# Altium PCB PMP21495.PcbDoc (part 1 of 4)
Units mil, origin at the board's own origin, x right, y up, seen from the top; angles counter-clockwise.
Board outline 10700 x 5800 mil, 6 copper layers (Top Layer, Signal Layer 3, Signal Layer 1, Signal Layer 2, Signal Layer 4, Bottom Layer), stack 66 mil thick; 305 components, 138 nets, 864 pads, 367 vias.
Unrouted connection lines stored in the file: 2.
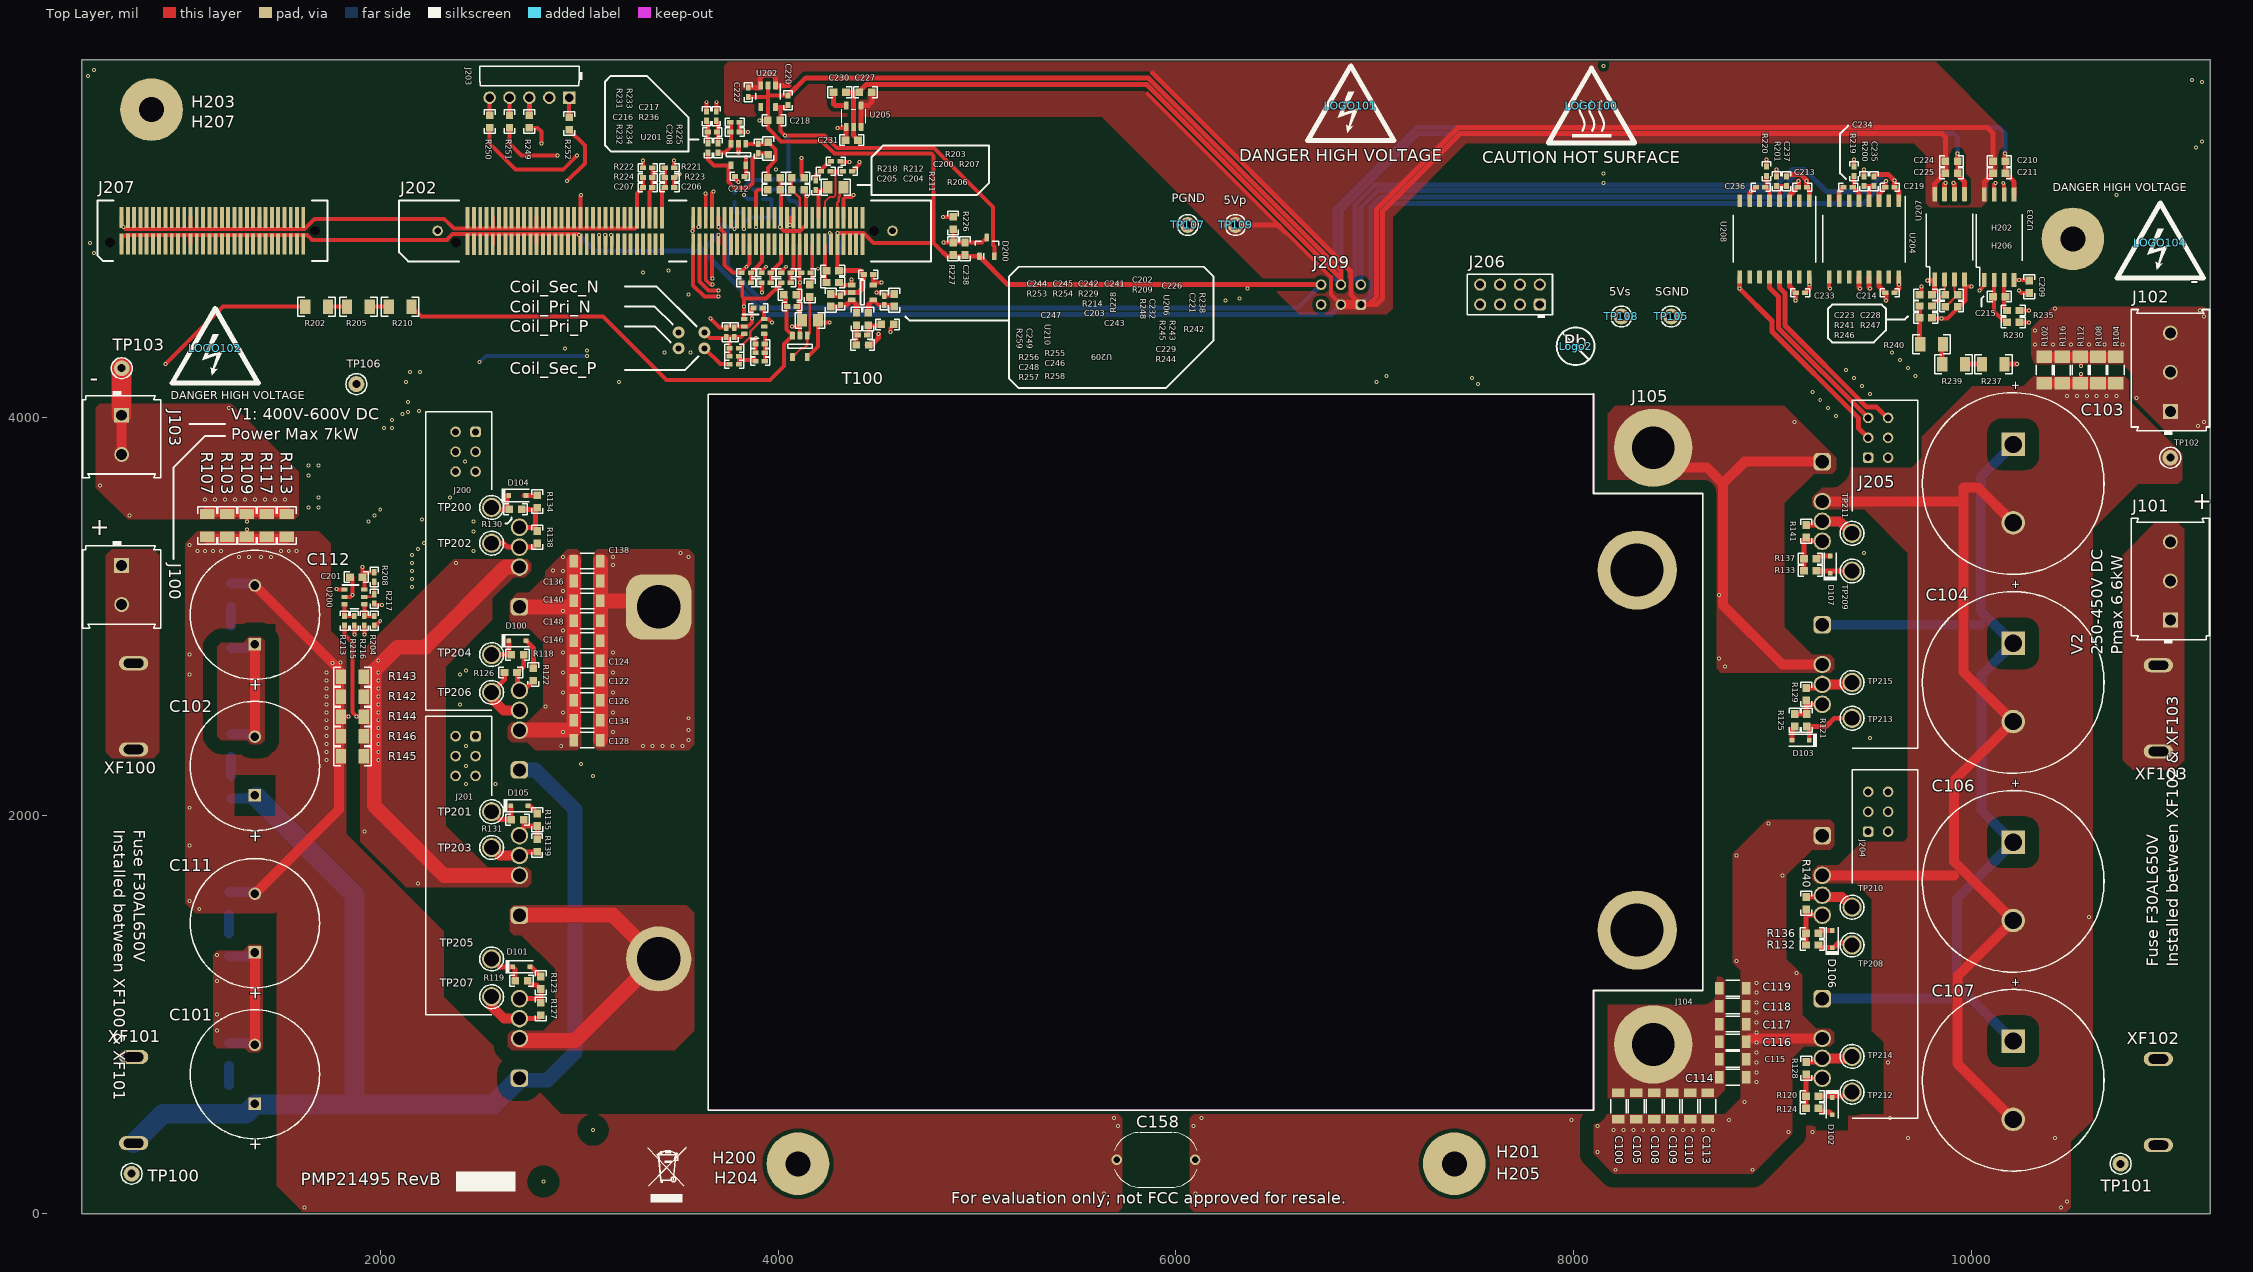
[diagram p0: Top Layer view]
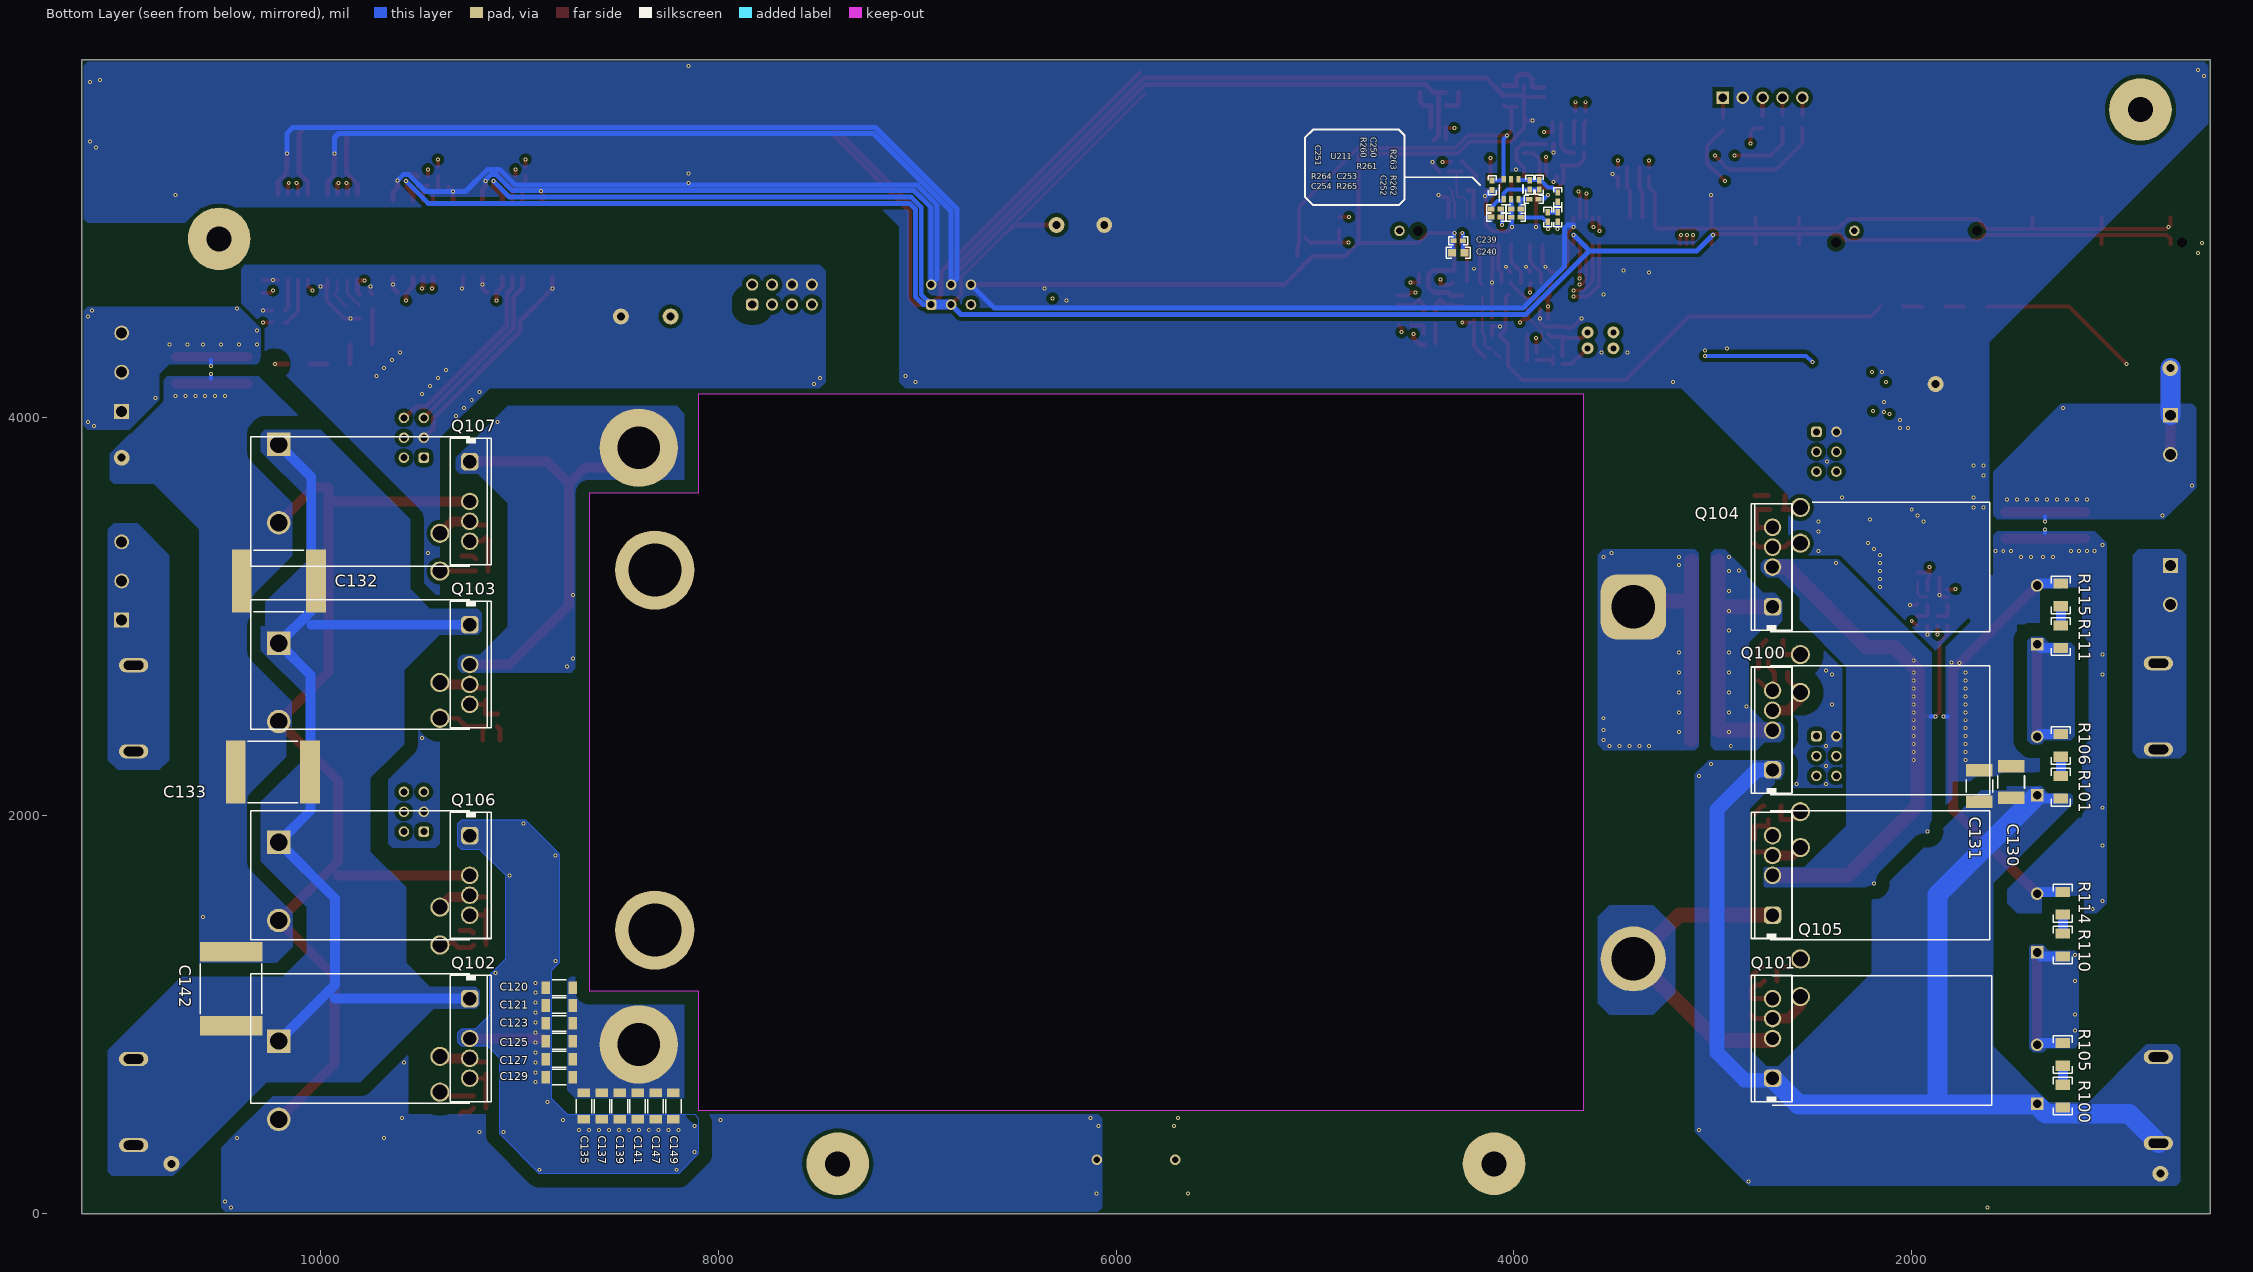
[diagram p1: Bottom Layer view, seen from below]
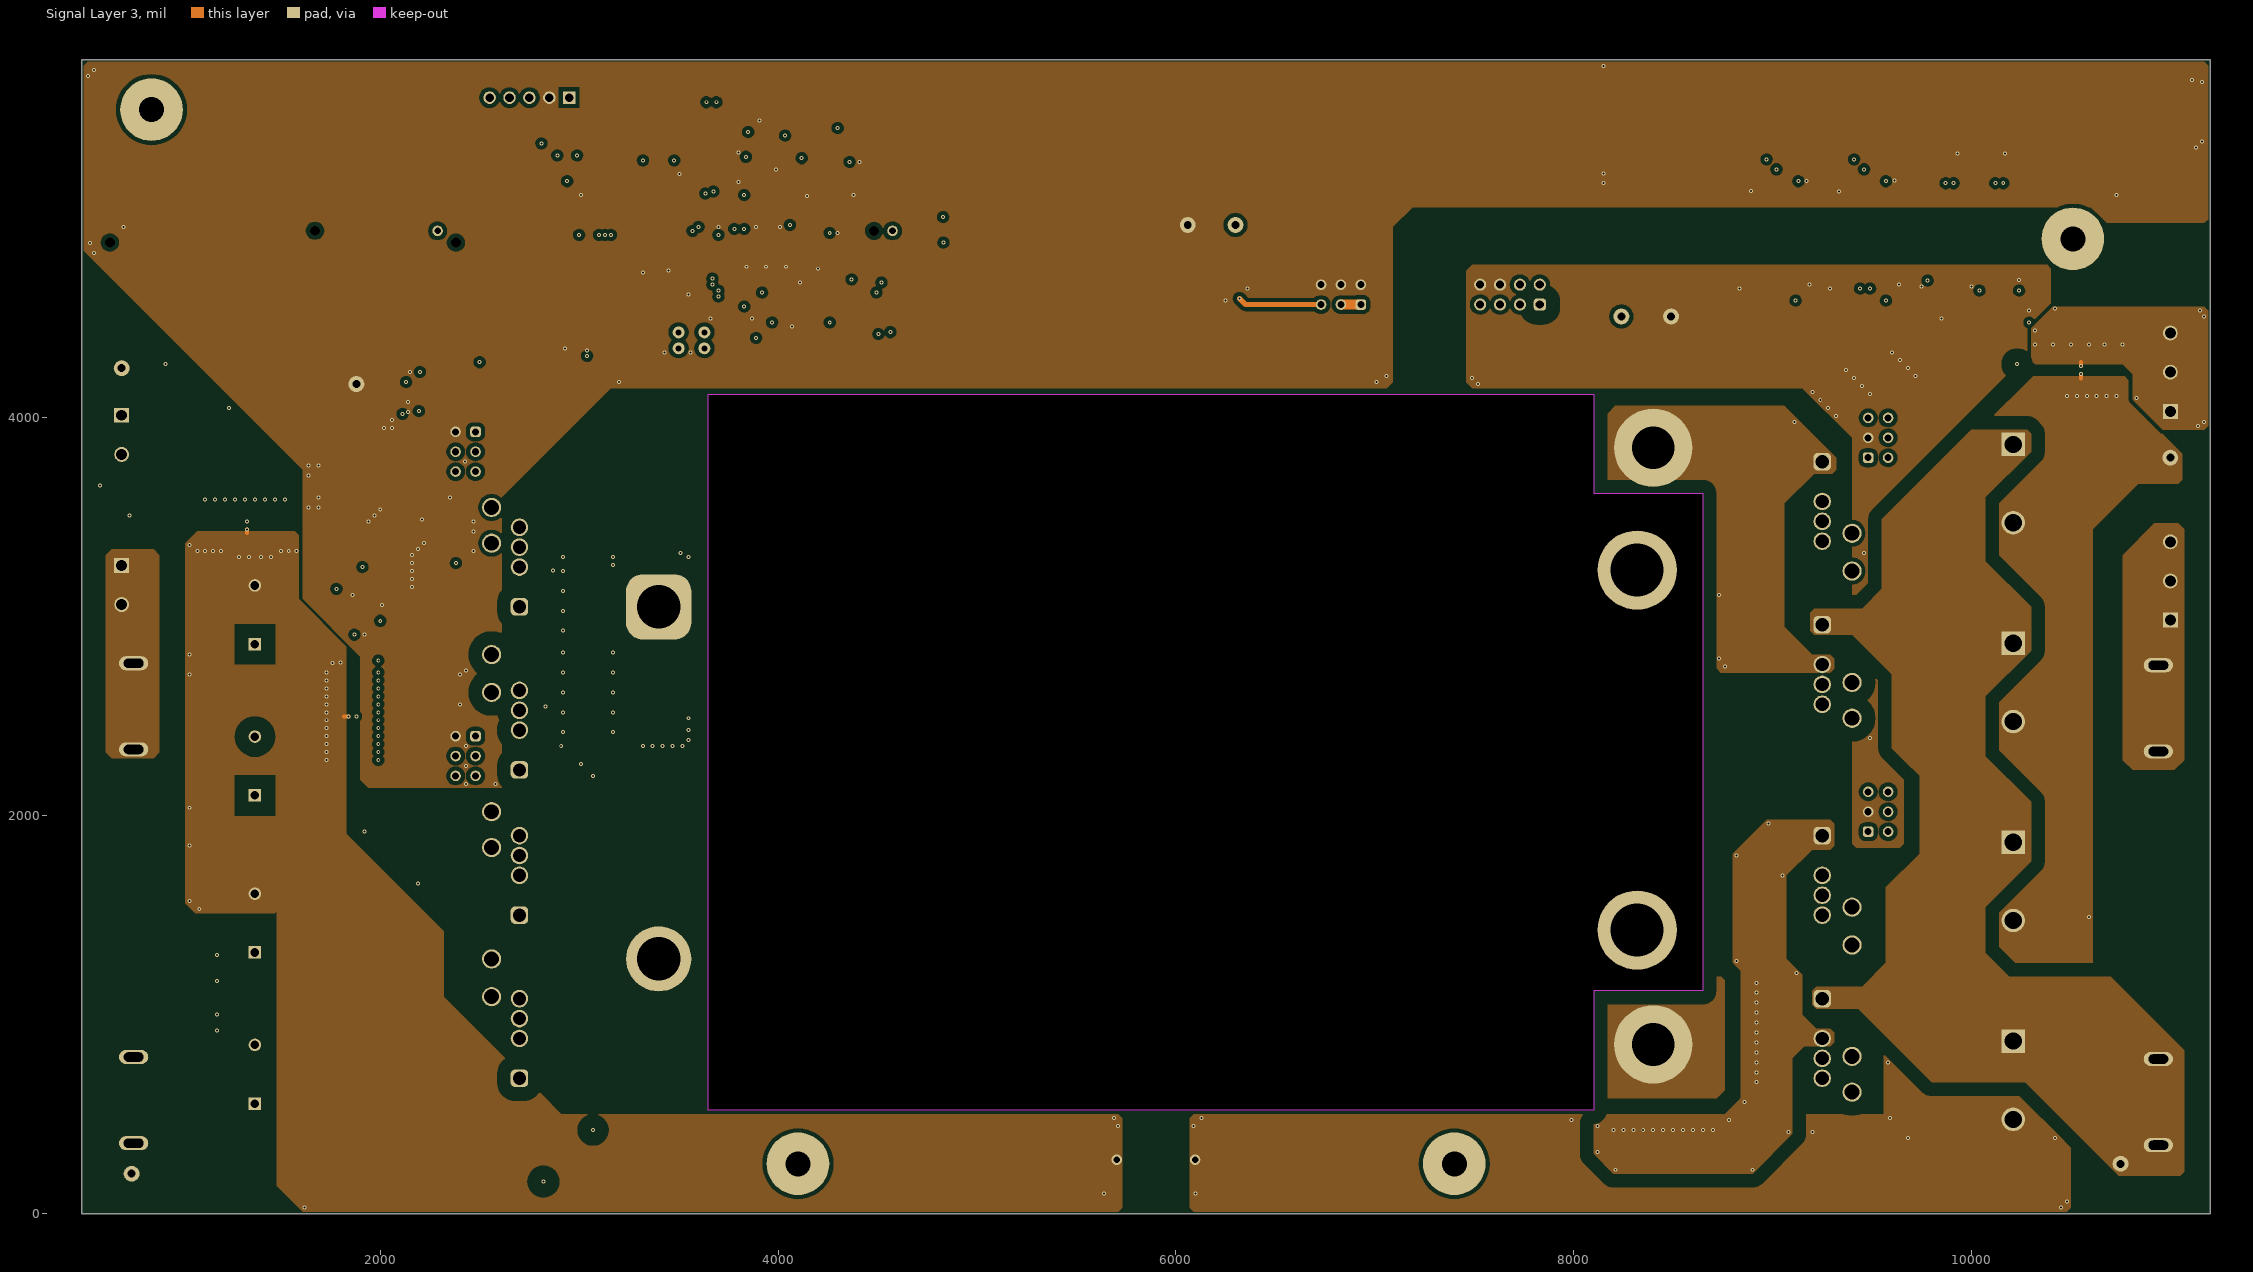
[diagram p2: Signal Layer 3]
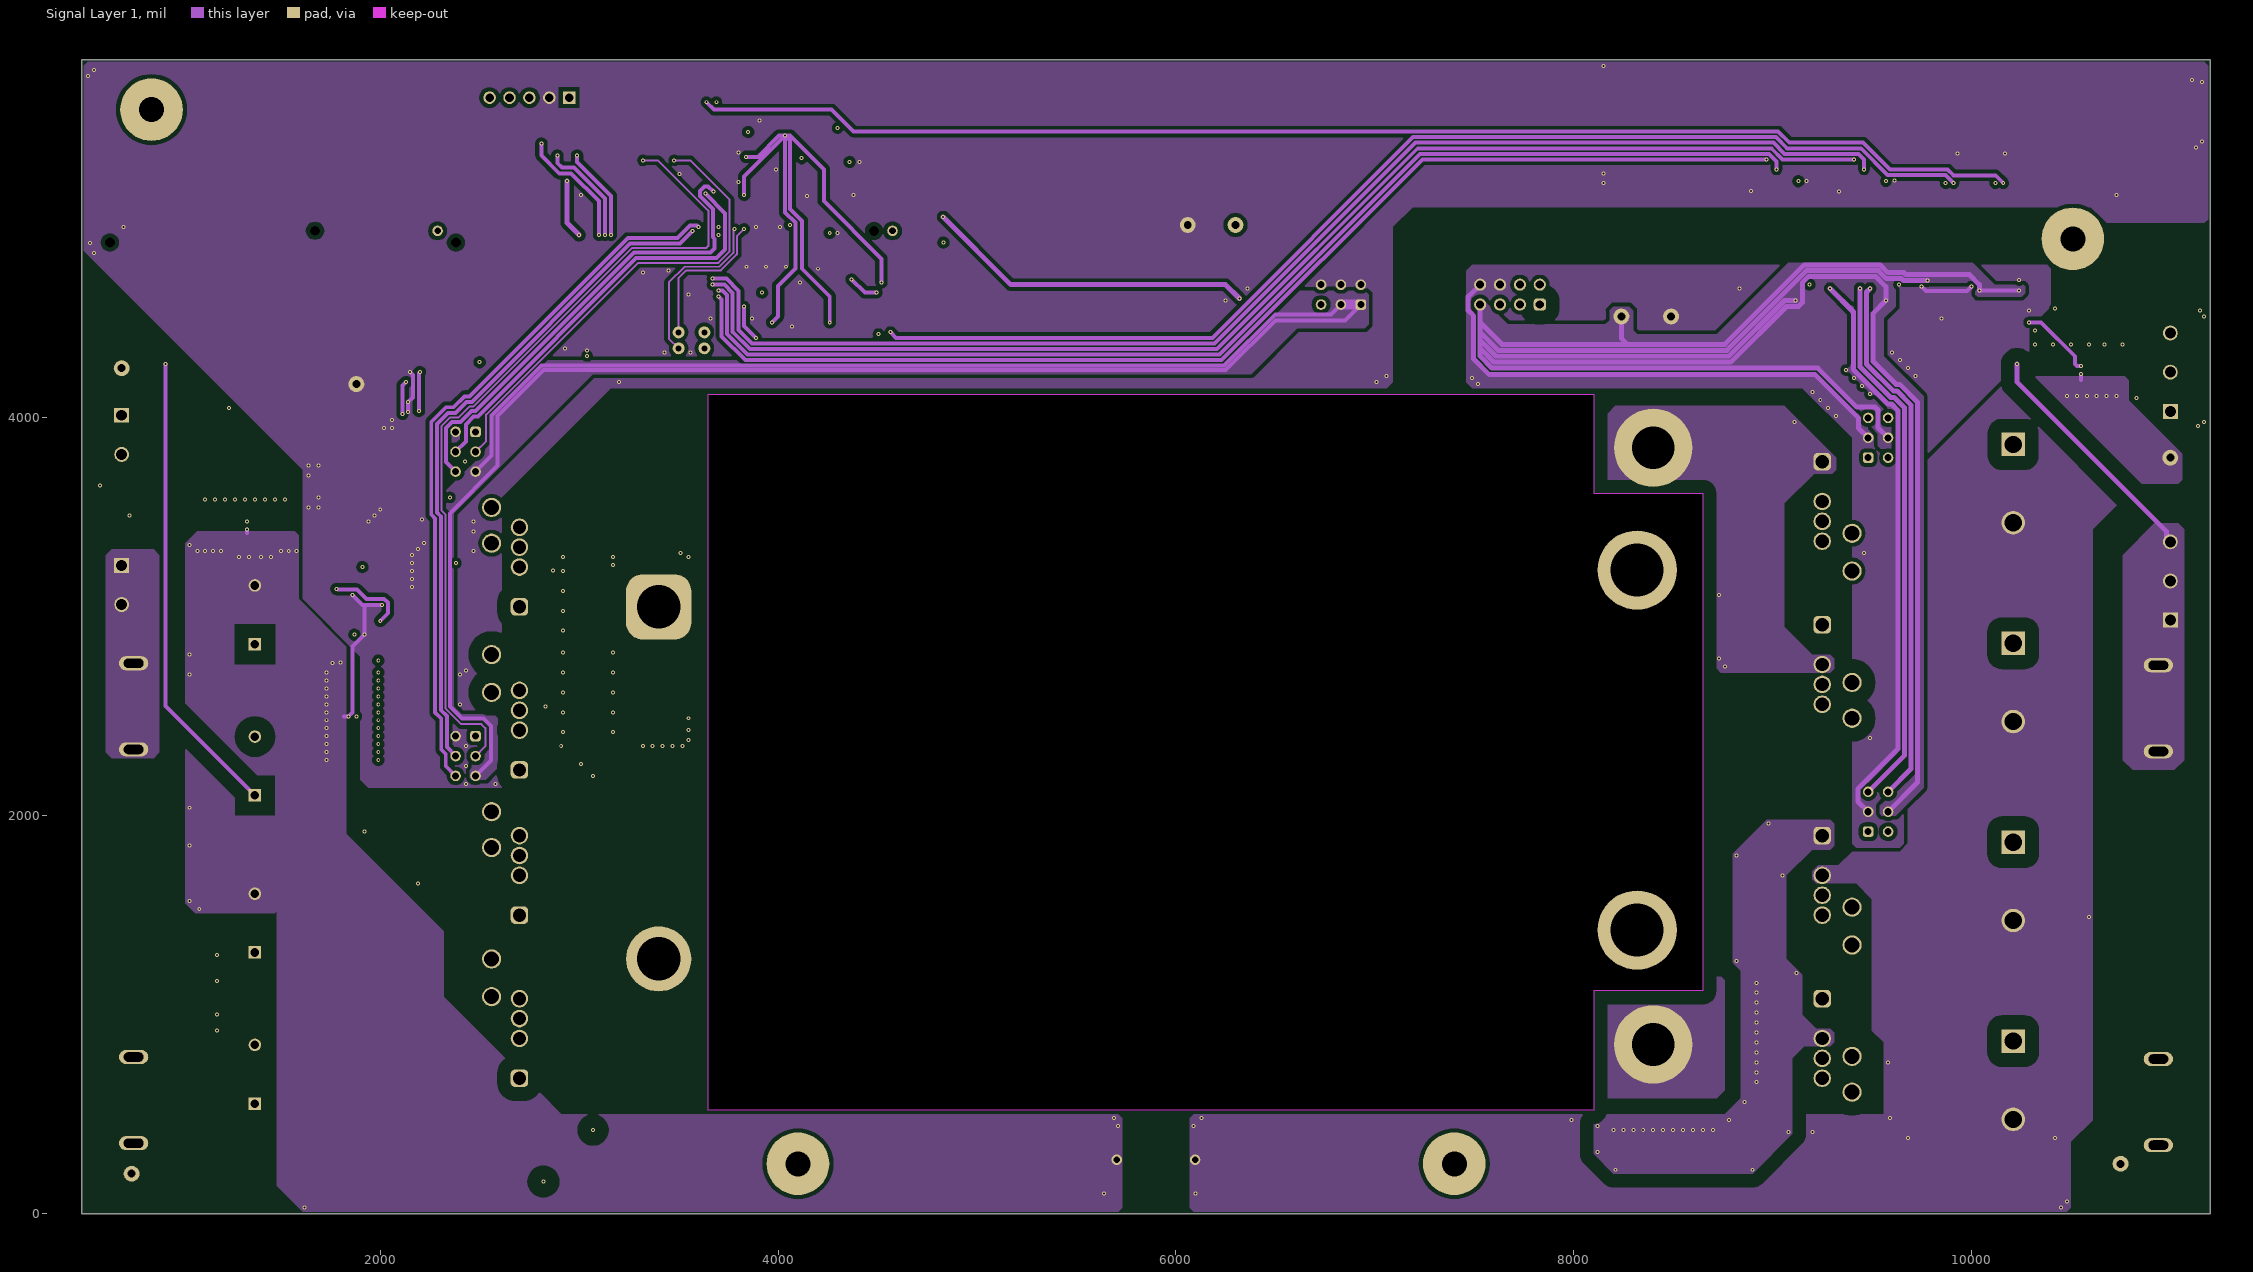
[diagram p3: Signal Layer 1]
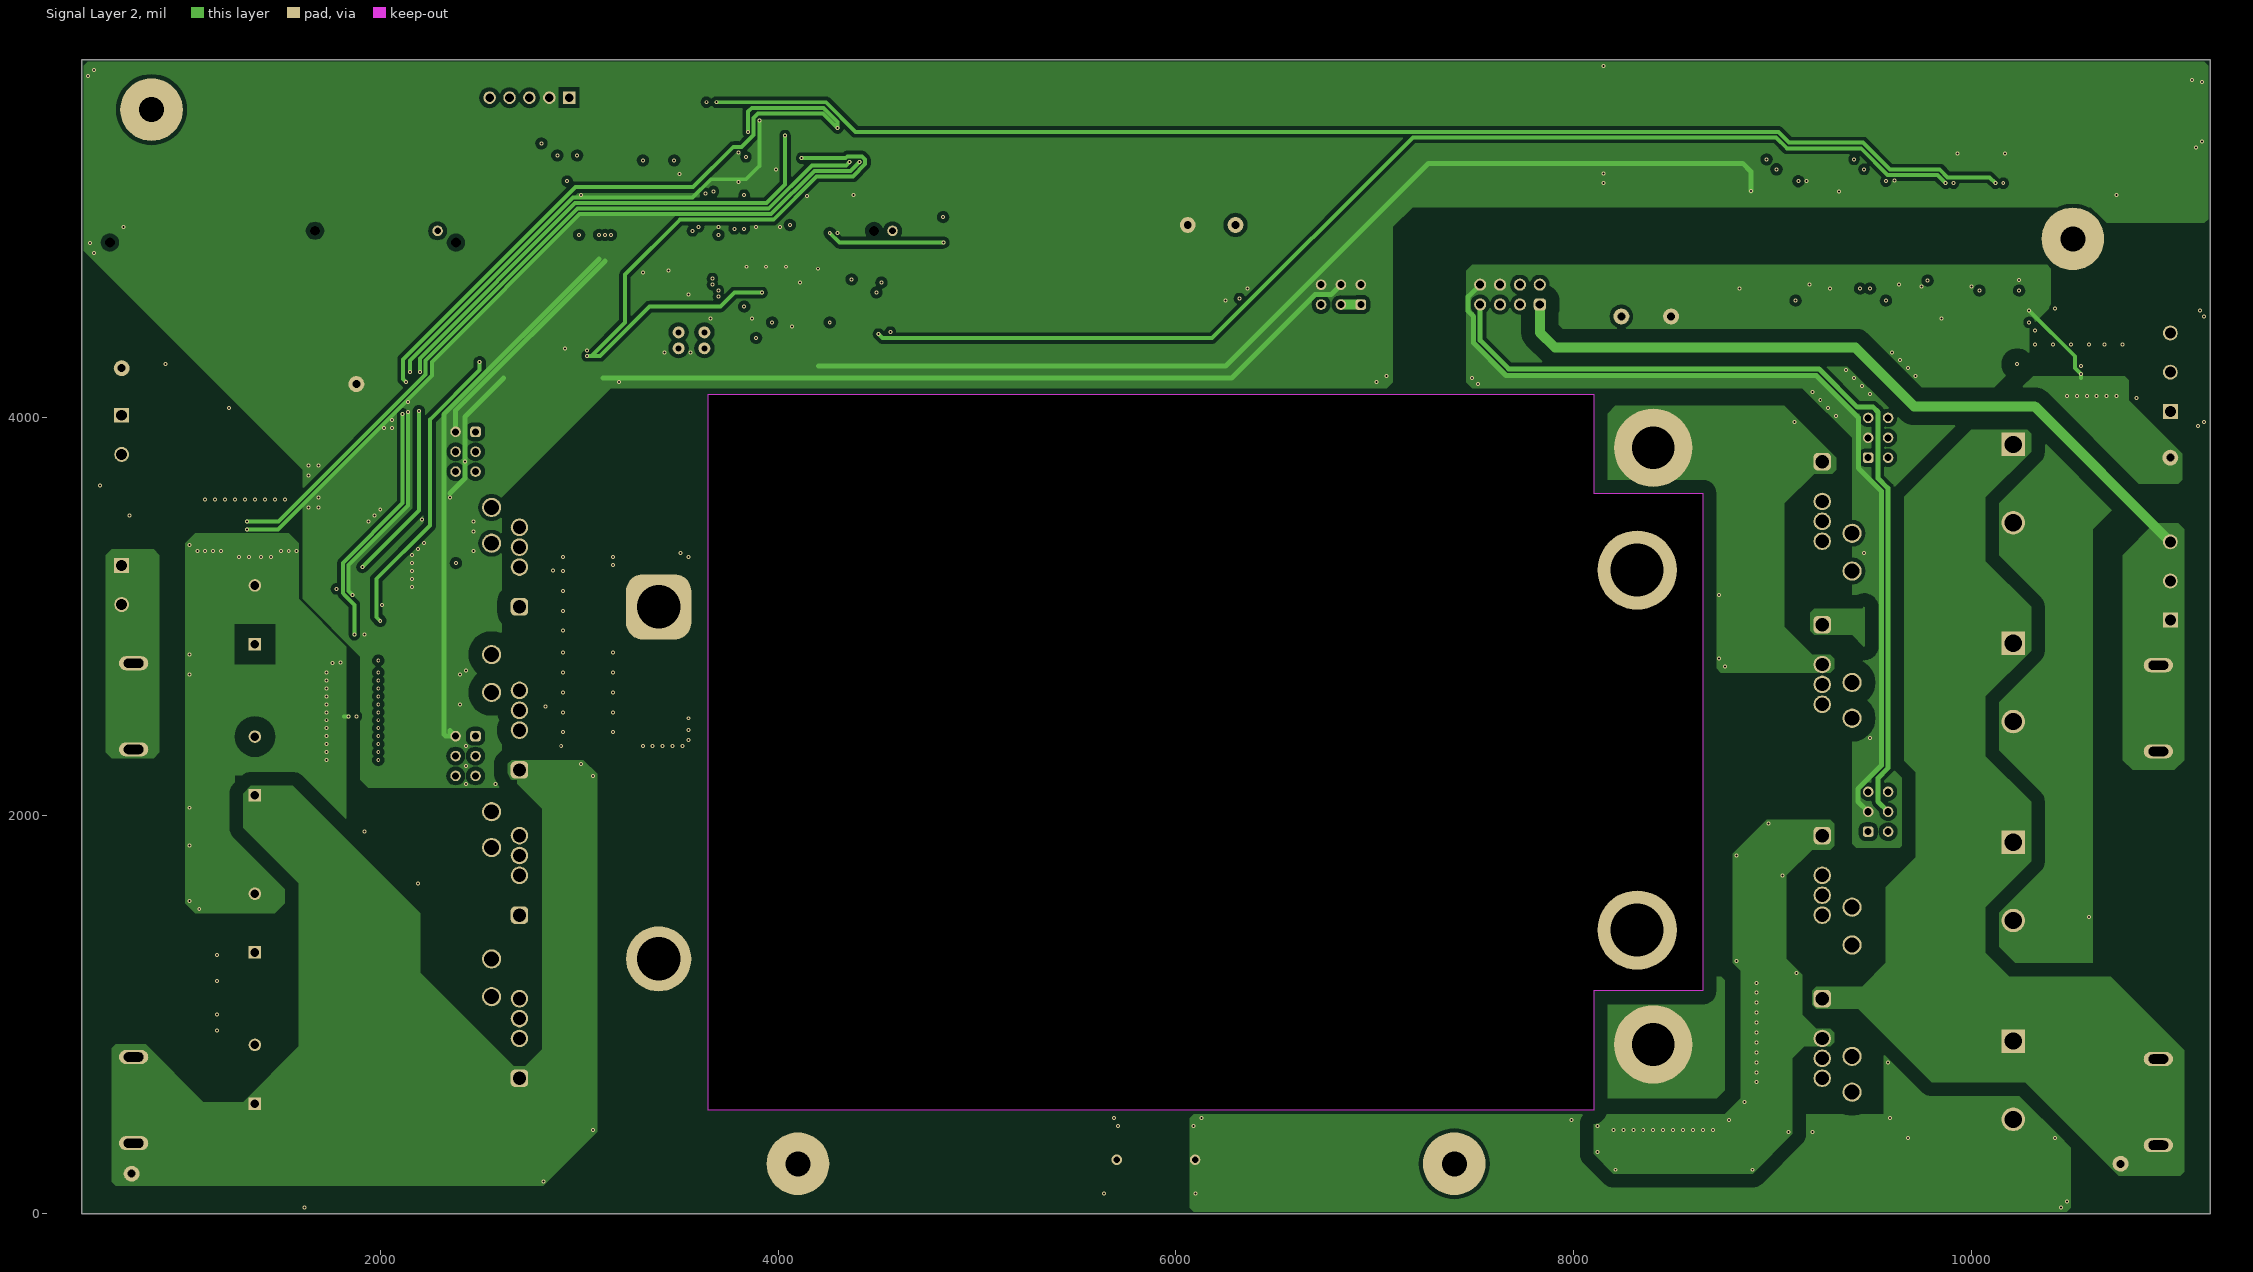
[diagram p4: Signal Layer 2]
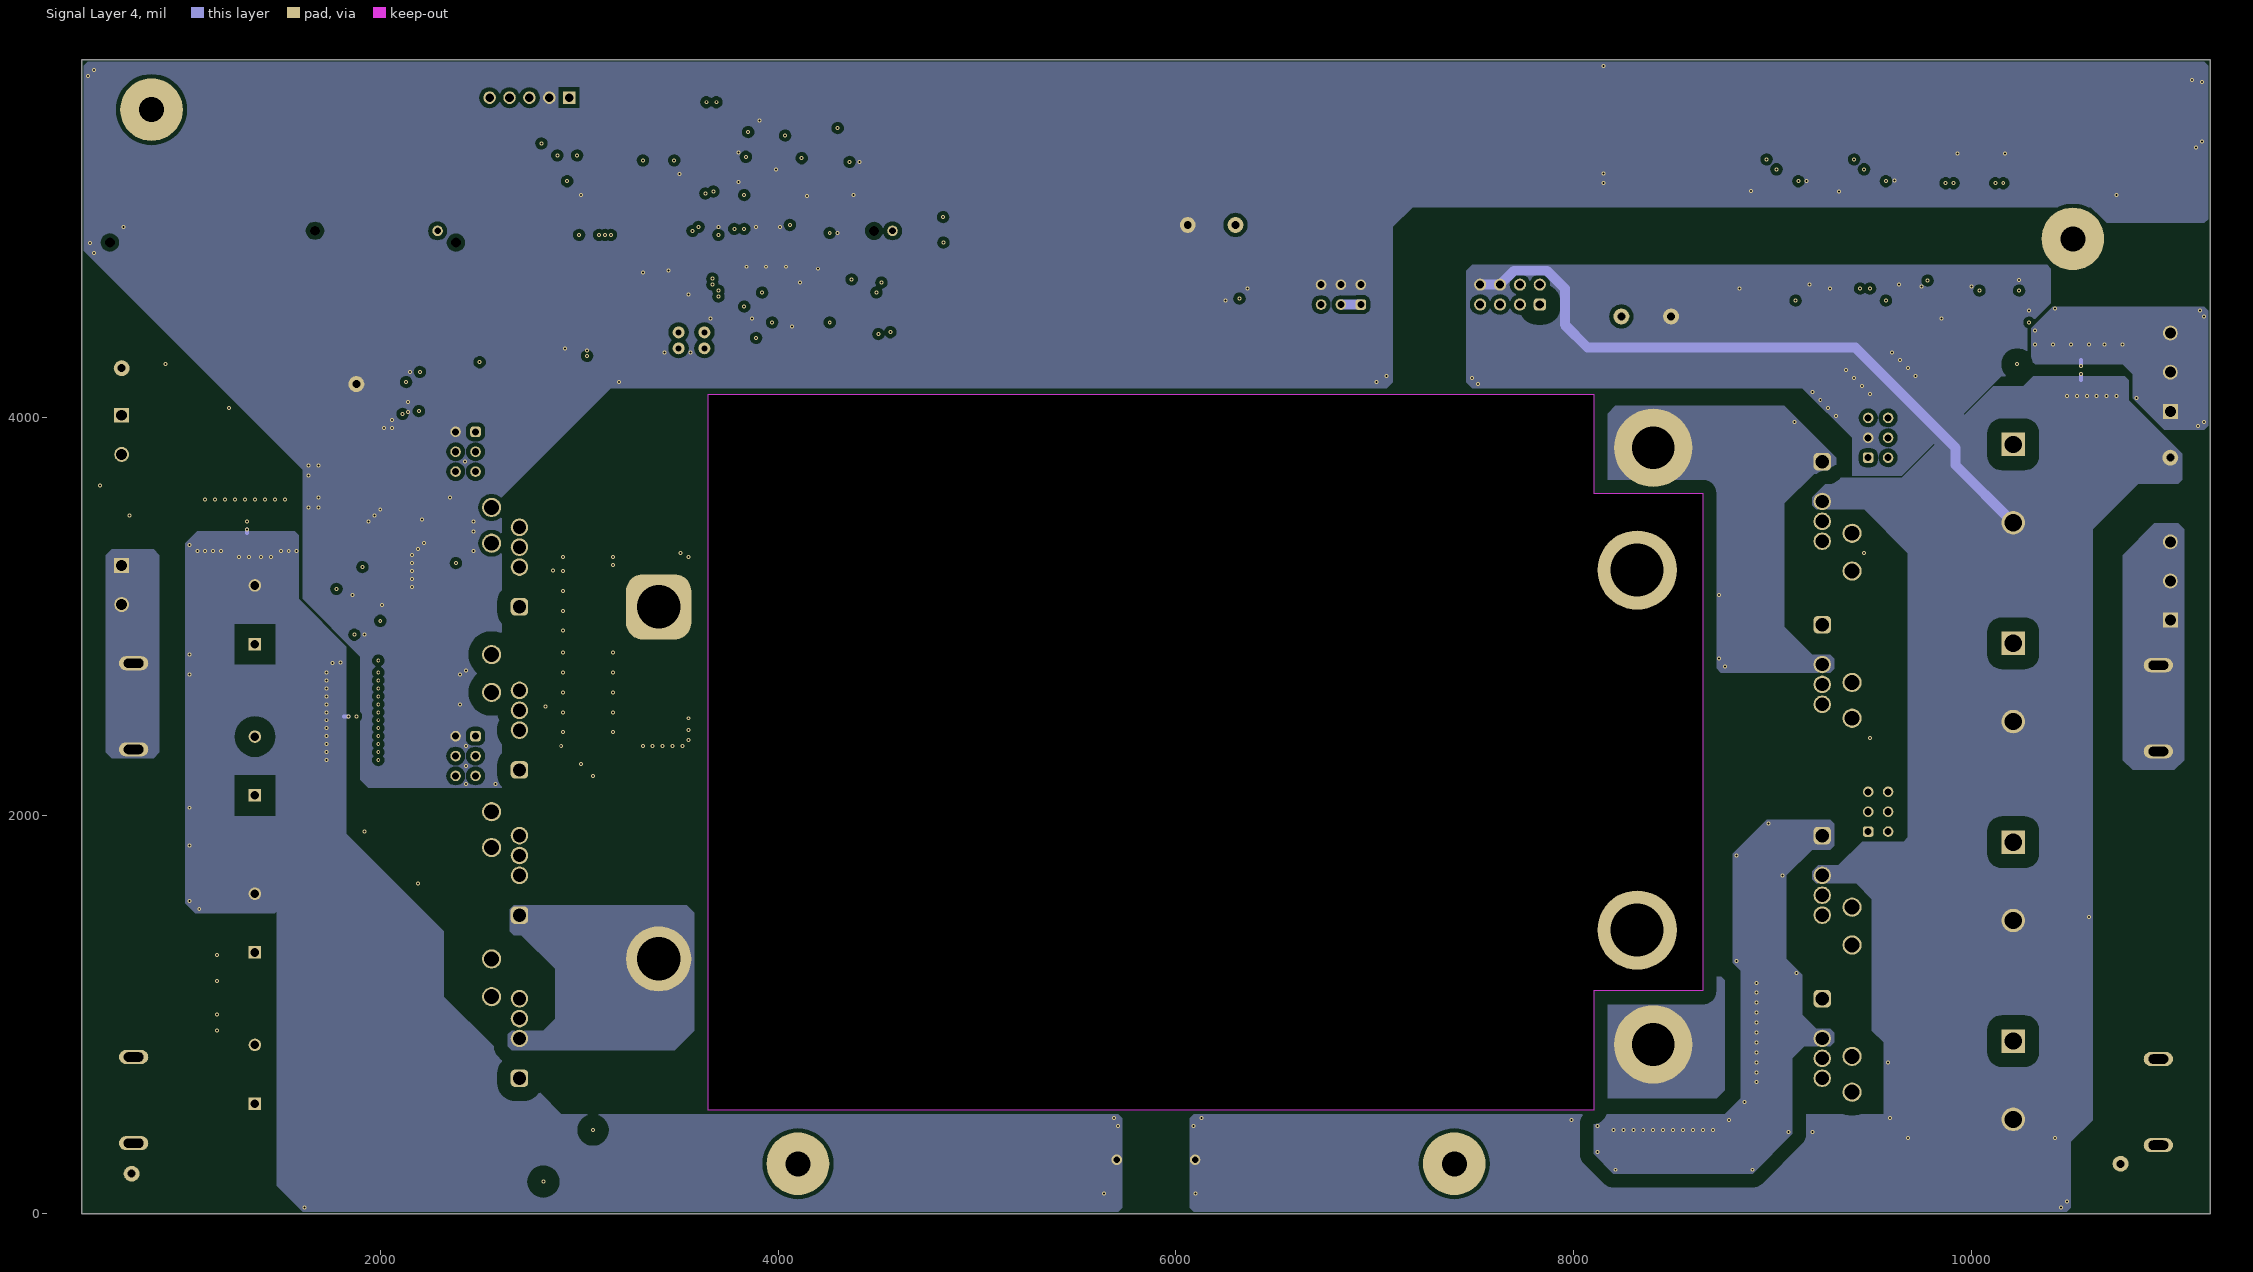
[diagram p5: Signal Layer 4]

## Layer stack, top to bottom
Top Solder: solder mask 0.4, Solder Resist, Dk 3.5
Top Layer: signal copper 4.2
Dielectric1: prepreg 8, Dk 4.2
Signal Layer 3: signal copper 1.4
Dielectric 4: core 14, FR-4, Dk 4.2
Signal Layer 1: signal copper 1.4
Dielectric 2: prepreg 8, Dk 4.2
Signal Layer 2: signal copper 1.4
Dielectric 5: core 14, FR-4, Dk 4.2
Signal Layer 4: signal copper 1.4
Dielectric 3: prepreg 8, Dk 4.2
Bottom Layer: signal copper 4.2
Bottom Solder: solder mask 0.4, Solder Resist, Dk 3.5

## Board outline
500,0 11200,0 11200,5800 500,5800
cut-out: 3648.66,520 3648.66,4120 8100,4120 8100,3620 8648.66,3620 8648.66,1120 8100,1120 8100,520

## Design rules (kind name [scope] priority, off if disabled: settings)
AcuteAngle [All] p1: minimum=4.50000000000000E+0001 checktracksonly=FALSE
AssemblyTestPointUsage [All] p1: valid=2
Clearance Clearance_2 [InNetClass('HV') vs Not InNetClass('HV')] p1: gap=70 ignorepadtopadclearanceinfootprint=FALSE
Clearance Clearance_1 [InNetClass('MV') vs Not InNetClass('MV')] p2: gap=40 ignorepadtopadclearanceinfootprint=FALSE
Clearance Clearance_Keepouts [((IsTrack Or IsArc) And Not InPoly) And IsFree and IsKeepOut vs ((IsTrack Or IsArc) And Not InPoly) And IsFree and IsKeepOut] p3: gap=0 ignorepadtopadclearanceinfootprint=FALSE
Clearance Clearance_BoardEdge_MountingHoles [OnCopper and InComponentClass('Mounting Holes') vs IsKeepOut] p4: gap=40 ignorepadtopadclearanceinfootprint=FALSE except(0: Arc-Hole Track-Hole SMDPad-Hole THPad-Hole Via-Hole Fill-Hole Poly-Hole Region-Hole Text-Hole)
Clearance Clearance_BoardEdge_Poly [OnCopper and InPoly vs IsKeepOut] p5: gap=25 ignorepadtopadclearanceinfootprint=FALSE except(0: Arc-Hole Track-Hole SMDPad-Hole THPad-Hole Via-Hole Fill-Hole Poly-Hole Region-Hole Text-Hole)
Clearance Clearance_BoardEdge [OnCopper and Not InComponentClass('Logo') and not InComponentClass('FiducialMark') and not InRegion(1000,500,4000,800) and Not IsKeepout vs IsKeepOut] p6: gap=75 ignorepadtopadclearanceinfootprint=FALSE except(0: Arc-Hole Track-Hole SMDPad-Hole THPad-Hole Via-Hole Fill-Hole Poly-Hole Region-Hole Text-Hole)
Clearance Clearance_Poly [InPolygon] p7: gap=20 ignorepadtopadclearanceinfootprint=FALSE except(0: Arc-Hole Track-Hole SMDPad-Hole THPad-Hole Via-Hole Fill-Hole Poly-Hole Region-Hole Text-Hole)
Clearance [All] p8: gap=7.87 ignorepadtopadclearanceinfootprint=FALSE except(0: Arc-Hole Track-Hole SMDPad-Hole THPad-Hole Via-Hole Fill-Hole Poly-Hole Region-Hole Text-Hole)
ComponentClearance ComponentClearance_MountingHoles_FiducialMarks [InComponentClass('Mounting Holes') vs InComponentClass('FiducialMark')] p1: gap=20 collisioncheckmode=3 verticalgap=10 showdistances=FALSE
ComponentClearance ComponentClearance_Shunt [InComponentClass('Header') vs InComponentClass('Shunt')] p2: gap=0 collisioncheckmode=3 verticalgap=0 showdistances=FALSE
ComponentClearance ComponentClearance_Logo [InComponentClass('Logo')] p3: gap=5 collisioncheckmode=3 verticalgap=10 showdistances=FALSE
ComponentClearance ComponentClearance_ScrewToNut [(HasFootprint('NY PMS 440 0025 PH')) vs (HasFootprint('Keystone_1902C'))] p4: gap=20 collisioncheckmode=3 verticalgap=100000 showdistances=FALSE
ComponentClearance ComponentClearance_MountingHoles [InComponentClass('Mounting Holes')] p5: gap=20 collisioncheckmode=3 verticalgap=10 showdistances=FALSE
ComponentClearance ComponentClearance_SmallPassives [HasFootprint('0201*') or HasFootprint('0402*') or HasFootprint('0508') or HasFootprint('0603*') or HasFootprint('0612') or HasFootprint('0805*') or HasFootprint('0815*') or HasFootprint('0830*') or HasFootprint('1206*') or HasFootprint('1210*') or HasFootprint('1808*') or HasFootprint('1812*') or HasFootprint('1825*') or HasFootprint('2010*') or HasFootprint('2220*') or HasFootprint('2225*') or HasFootprint('2512*') or HasFootprint('2728*') or HasFootprint('3518*') vs HasFootprint('0201*') or HasFootprint('0402*') or HasFootprint('0508') or HasFootprint('0603*') or HasFootprint('0612') or HasFootprint('0805*') or HasFootprint('0815*') or HasFootprint('0830*') or HasFootprint('1206*') or HasFootprint('1210*') or HasFootprint('1808*') or HasFootprint('1812*') or HasFootprint('1825*') or HasFootprint('2010*') or HasFootprint('2220*') or HasFootprint('2225*') or HasFootprint('2512*') or HasFootprint('2728*') or HasFootprint('3518*')] p6: gap=10 collisioncheckmode=3 verticalgap=10 showdistances=FALSE
ComponentClearance ComponentClearance_THtoSMT [IsThruComponent vs IsSMTComponent] p7: gap=10 collisioncheckmode=3 verticalgap=10 showdistances=FALSE
ComponentClearance ComponentClearance_THtoTH [IsThruComponent vs IsThruComponent] p8: gap=10 collisioncheckmode=3 verticalgap=10 showdistances=FALSE
ComponentClearance [All] p9: gap=10 collisioncheckmode=3 verticalgap=10 showdistances=FALSE
DiffPairsRouting [All] p1: maxlimit=100 minlimit=10 mostfreqgap=10 toplayer_minwidth=15 toplayer_maxwidth=15 toplayer_prefwidth=15 midlayer1_minwidth=15 midlayer1_maxwidth=15 midlayer1_prefwidth=15 midlayer2_minwidth=15 midlayer2_maxwidth=15 midlayer2_prefwidth=15 midlayer3_minwidth=15 midlayer3_maxwidth=15 midlayer3_prefwidth=15 midlayer4_minwidth=15 midlayer4_maxwidth=15 midlayer4_prefwidth=15 bottomlayer_minwidth=15 bottomlayer_maxwidth=15 bottomlayer_prefwidth=15 maxuncoupledlength=1000
FabricationTestPointUsage TestPointUsage [All] p1: valid=2 allowmultiple=FALSE
FabricationTestpoint Testpoint [All] p1: side=3 testpointundercomponent=TRUE minsize=40 maxsize=100 preferedsize=60 minholesize=0 maxholesize=40 preferedholesize=32 testpointgrid=1 allowsidetop=TRUE allowsidebottom=TRUE usegrid=TRUE gridtolerance=0.01
FanoutControl Fanout_LCC [IsLCC] p1: bgadir=Out bgaviamode=Centered fanoutstyle=Auto fanoutdirection=Alternating viagrid=1 // Fanout_LCC (Default Rule)
FanoutControl Fanout_BGA [IsBGA] p2: bgadir=Out bgaviamode=Centered fanoutstyle=Auto fanoutdirection=Alternating viagrid=1 // Fanout_BGA (Default Rule)
FanoutControl Fanout_Default [All] p4: bgadir=Out bgaviamode=Centered fanoutstyle=Auto fanoutdirection=Alternating viagrid=1 // Fanout_Default (Default Rule)
FanoutControl Fanout_Small [(CompPinCount < 5)] p5: bgadir=Out bgaviamode=Centered fanoutstyle=Auto fanoutdirection=OutThenIn viagrid=1 // Fanout_Small (Default Rule)
Height [All] p1: minheight=0 maxheight=3000 prefheight=500
HoleSize [All] p1: absolutevalues=TRUE maxlimit=251 minlimit=7 maxpercent=80.000 minpercent=20.000
MinimumAnnularRing MinimumAnnularRing_ThermalPadVias [IsVia and InAnyComponent] p1: minimumring=5.91
MinimumAnnularRing [All] p2: minimumring=4.9
MinimumSolderMaskSliver MinimumSolderMaskSliver_Logo [InComponentClass('Logo') vs InComponentClass('Logo')] p1: minsoldermaskwidth=0.7
MinimumSolderMaskSliver [All] p2: minsoldermaskwidth=2
PlaneConnect [All] p1: planeconnectstyle=Direct reliefexpansion=10 reliefentries=4 reliefconductorwidth=10 reliefairgap=10
PolygonConnect PolygonConnect_23 [All vs IsNamedPolygon('RTN') Or  IsNamedPolygon('CS') Or  IsNamedPolygon('C122_1') Or  IsNamedPolygon('C122_1') Or  IsNamedPolygon('C102_2') Or  IsNamedPolygon('VBUS') Or  IsNamedPolygon('HVBUS') Or  IsNamedPolygon('Q101_2') Or  IsNamedPolygon('Q101_2') Or  IsNamedPolygon('C103_1') Or  IsNamedPolygon('C122_2') Or  IsNamedPolygon('VBATT') Or  IsNamedPolygon('BATT_RTN') Or  IsNamedPolygon('SGND') Or  IsNamedPolygon('C100_1') Or  IsNamedPolygon('C122_2') Or  IsNamedPolygon('PGND') Or  IsNamedPolygon('C100_1') Or  IsNamedPolygon('PGND') Or  IsNamedPolygon('C103_1') Or  IsNamedPolygon('C103_1') Or  IsNamedPolygon('C103_1') Or  IsNamedPolygon('J105_1') Or  IsNamedPolygon('VBATT') Or  IsNamedPolygon('BATT_RTN') Or  IsNamedPolygon('J105_1') Or  IsNamedPolygon('HVBUS') Or  IsNamedPolygon('Q101_2') Or  IsNamedPolygon('RTN') Or  IsNamedPolygon('C102_2') Or  IsNamedPolygon('C101_2') Or  IsNamedPolygon('CS') Or  IsNamedPolygon('C103_1') Or  IsNamedPolygon('C101_2') Or  IsNamedPolygon('C100_2') Or  IsNamedPolygon('C100_2') Or  IsNamedPolygon('5Vs') Or  IsNamedPolygon('VBUS') Or  IsNamedPolygon('VBUS') Or  IsNamedPolygon('J105_1') Or  IsNamedPolygon('J105_1') Or  IsNamedPolygon('J105_1') Or  IsNamedPolygon('VBUS') Or  IsNamedPolygon('VBUS') Or  IsNamedPolygon('J105_1') Or  IsNamedPolygon('C100_2') Or  IsNamedPolygon('C100_1') Or  IsNamedPolygon('C103_1') Or  IsNamedPolygon('C100_1') Or  IsNamedPolygon('C100_1') Or  IsNamedPolygon('C100_2') Or  IsNamedPolygon('C100_1') Or  IsNamedPolygon('C100_2') Or  IsNamedPolygon('C100_2') Or  IsNamedPolygon('C100_1') Or  IsNamedPolygon('C100_1') Or  IsNamedPolygon('PGND') Or  IsNamedPolygon('SGND') Or  IsNamedPolygon('SGND') Or  IsNamedPolygon('SGND') Or  IsNamedPolygon('SGND') Or  IsNamedPolygon('SGND') Or  IsNamedPolygon('VBATT') Or  IsNamedPolygon('SGND') Or  IsNamedPolygon('SGND') Or  IsNamedPolygon('PGND') Or  IsNamedPolygon('SGND') Or  IsNamedPolygon('SGND') Or  IsNamedPolygon('SGND') Or  IsNamedPolygon('PGND') Or  IsNamedPolygon('SGND') Or  IsNamedPolygon('VBATT') Or  IsNamedPolygon('SGND') Or  IsNamedPolygon('PGND') Or  IsNamedPolygon('PGND') Or  IsNamedPolygon('SGND') Or  IsNamedPolygon('PGND') Or  IsNamedPolygon('SGND') Or  IsNamedPolygon('SGND') Or  IsNamedPolygon('PGND') Or  IsNamedPolygon('BATT_RTN') Or  IsNamedPolygon('SGND') Or  IsNamedPolygon('SGND') Or  IsNamedPolygon('PGND') Or  IsNamedPolygon('BATT_RTN') Or  IsNamedPolygon('PGND') Or  IsNamedPolygon('PGND') Or  IsNamedPolygon('PGND') Or  IsNamedPolygon('PGND') Or  IsNamedPolygon('PGND') Or  IsNamedPolygon('PGND') Or  IsNamedPolygon('VBATT') Or  IsNamedPolygon('5Vp') Or  IsNamedPolygon('VBATT') Or  IsNamedPolygon('VBUS') Or  IsNamedPolygon('5Vp') Or  IsNamedPolygon('5Vp')] p1: connectstyle=Direct reliefconductorwidth=10 reliefentries=4 polygonreliefangle="90 Angle" airgapwidth=10
PolygonConnect PolygonConnect_22 [All vs IsNamedPolygon('PGND') Or  IsNamedPolygon('VBATT') Or  IsNamedPolygon('VBATT') Or  IsNamedPolygon('VBATT') Or  IsNamedPolygon('RTN') Or  IsNamedPolygon('PGND') Or  IsNamedPolygon('C100_1') Or  IsNamedPolygon('SGND') Or  IsNamedPolygon('VBATT') Or  IsNamedPolygon('VBUS') Or  IsNamedPolygon('VBATT') Or  IsNamedPolygon('C103_1') Or  IsNamedPolygon('PGND') Or  IsNamedPolygon('PGND') Or  IsNamedPolygon('C100_1') Or  IsNamedPolygon('VBUS') Or  IsNamedPolygon('PGND') Or  IsNamedPolygon('SGND') Or  IsNamedPolygon('PGND') Or  IsNamedPolygon('J105_1') Or  IsNamedPolygon('SGND') Or  IsNamedPolygon('C100_2') Or  IsNamedPolygon('C100_2') Or  IsNamedPolygon('C100_2') Or  IsNamedPolygon('SGND') Or  IsNamedPolygon('J105_1') Or  IsNamedPolygon('SGND') Or  IsNamedPolygon('SGND') Or  IsNamedPolygon('PGND') Or  IsNamedPolygon('J105_1') Or  IsNamedPolygon('PGND') Or  IsNamedPolygon('C100_1') Or  IsNamedPolygon('SGND') Or  IsNamedPolygon('C100_1') Or  IsNamedPolygon('SGND') Or  IsNamedPolygon('PGND') Or  IsNamedPolygon('BATT_RTN') Or  IsNamedPolygon('J105_1') Or  IsNamedPolygon('PGND') Or  IsNamedPolygon('VBUS') Or  IsNamedPolygon('SGND') Or  IsNamedPolygon('C100_1') Or  IsNamedPolygon('PGND') Or  IsNamedPolygon('J105_1') Or  IsNamedPolygon('C103_1') Or  IsNamedPolygon('SGND') Or  IsNamedPolygon('PGND') Or  IsNamedPolygon('SGND') Or  IsNamedPolygon('SGND') Or  IsNamedPolygon('SGND') Or  IsNamedPolygon('C100_2') Or  IsNamedPolygon('C100_2') Or  IsNamedPolygon('BATT_RTN') Or  IsNamedPolygon('SGND') Or  IsNamedPolygon('PGND') Or  IsNamedPolygon('C103_1') Or  IsNamedPolygon('C100_1') Or  IsNamedPolygon('VBUS') Or  IsNamedPolygon('PGND') Or  IsNamedPolygon('VBATT') Or  IsNamedPolygon('Q101_2') Or  IsNamedPolygon('C103_1') Or  IsNamedPolygon('C103_1') Or  IsNamedPolygon('PGND') Or  IsNamedPolygon('5Vp') Or  IsNamedPolygon('RTN') Or  IsNamedPolygon('C103_1') Or  IsNamedPolygon('SGND') Or  IsNamedPolygon('5Vp') Or  IsNamedPolygon('J105_1') Or  IsNamedPolygon('SGND') Or  IsNamedPolygon('SGND') Or  IsNamedPolygon('C100_1') Or  IsNamedPolygon('HVBUS') Or  IsNamedPolygon('C100_1') Or  IsNamedPolygon('BATT_RTN') Or  IsNamedPolygon('C102_2') Or  IsNamedPolygon('Q101_2') Or  IsNamedPolygon('PGND') Or  IsNamedPolygon('BATT_RTN') Or  IsNamedPolygon('SGND') Or  IsNamedPolygon('C100_2') Or  IsNamedPolygon('VBUS') Or  IsNamedPolygon('C122_1') Or  IsNamedPolygon('C101_2') Or  IsNamedPolygon('CS') Or  IsNamedPolygon('HVBUS') Or  IsNamedPolygon('CS') Or  IsNamedPolygon('C122_2') Or  IsNamedPolygon('C101_2') Or  IsNamedPolygon('VBUS') Or  IsNamedPolygon('Q101_2') Or  IsNamedPolygon('C122_2') Or  IsNamedPolygon('C122_1') Or  IsNamedPolygon('C102_2')] p2: connectstyle=Direct reliefconductorwidth=10 reliefentries=4 polygonreliefangle="90 Angle" airgapwidth=10
PolygonConnect PolygonConnect_21 [All vs IsNamedPolygon('SGND') Or  IsNamedPolygon('SGND') Or  IsNamedPolygon('SGND') Or  IsNamedPolygon('PGND') Or  IsNamedPolygon('SGND') Or  IsNamedPolygon('SGND') Or  IsNamedPolygon('PGND') Or  IsNamedPolygon('SGND') Or  IsNamedPolygon('PGND') Or  IsNamedPolygon('PGND') Or  IsNamedPolygon('SGND') Or  IsNamedPolygon('SGND') Or  IsNamedPolygon('SGND') Or  IsNamedPolygon('SGND') Or  IsNamedPolygon('SGND') Or  IsNamedPolygon('SGND') Or  IsNamedPolygon('SGND') Or  IsNamedPolygon('C100_2') Or  IsNamedPolygon('C100_2') Or  IsNamedPolygon('VBATT') Or  IsNamedPolygon('C101_2') Or  IsNamedPolygon('C100_2') Or  IsNamedPolygon('C100_2') Or  IsNamedPolygon('SGND') Or  IsNamedPolygon('PGND') Or  IsNamedPolygon('PGND') Or  IsNamedPolygon('PGND') Or  IsNamedPolygon('C102_2') Or  IsNamedPolygon('BATT_RTN') Or  IsNamedPolygon('PGND') Or  IsNamedPolygon('CS') Or  IsNamedPolygon('PGND') Or  IsNamedPolygon('VBUS') Or  IsNamedPolygon('J105_1') Or  IsNamedPolygon('PGND') Or  IsNamedPolygon('C102_2') Or  IsNamedPolygon('VBATT') Or  IsNamedPolygon('J105_1') Or  IsNamedPolygon('C103_1') Or  IsNamedPolygon('VBUS') Or  IsNamedPolygon('C103_1') Or  IsNamedPolygon('C103_1') Or  IsNamedPolygon('J105_1') Or  IsNamedPolygon('VBUS') Or  IsNamedPolygon('C122_1') Or  IsNamedPolygon('C103_1') Or  IsNamedPolygon('PGND') Or  IsNamedPolygon('VBUS') Or  IsNamedPolygon('SGND') Or  IsNamedPolygon('RTN') Or  IsNamedPolygon('BATT_RTN') Or  IsNamedPolygon('Q101_2') Or  IsNamedPolygon('C122_2') Or  IsNamedPolygon('C103_1') Or  IsNamedPolygon('PGND') Or  IsNamedPolygon('C100_1') Or  IsNamedPolygon('C122_2') Or  IsNamedPolygon('C100_2') Or  IsNamedPolygon('BATT_RTN') Or  IsNamedPolygon('PGND') Or  IsNamedPolygon('VBATT') Or  IsNamedPolygon('C100_1') Or  IsNamedPolygon('C101_2') Or  IsNamedPolygon('C100_2') Or  IsNamedPolygon('RTN') Or  IsNamedPolygon('VBATT') Or  IsNamedPolygon('C100_1') Or  IsNamedPolygon('VBATT') Or  IsNamedPolygon('C100_1') Or  IsNamedPolygon('C122_1') Or  IsNamedPolygon('VBATT') Or  IsNamedPolygon('PGND') Or  IsNamedPolygon('VBUS') Or  IsNamedPolygon('J105_1') Or  IsNamedPolygon('SGND') Or  IsNamedPolygon('HVBUS') Or  IsNamedPolygon('J105_1') Or  IsNamedPolygon('C100_1') Or  IsNamedPolygon('HVBUS') Or  IsNamedPolygon('Q101_2') Or  IsNamedPolygon('C100_1') Or  IsNamedPolygon('J105_1') Or  IsNamedPolygon('BATT_RTN') Or  IsNamedPolygon('VBUS') Or  IsNamedPolygon('CS') Or  IsNamedPolygon('C100_1') Or  IsNamedPolygon('PGND') Or  IsNamedPolygon('PGND') Or  IsNamedPolygon('Q101_2') Or  IsNamedPolygon('C103_1') Or  IsNamedPolygon('C100_1') Or  IsNamedPolygon('PGND')] p3: connectstyle=Direct reliefconductorwidth=10 reliefentries=4 polygonreliefangle="90 Angle" airgapwidth=10
PolygonConnect PolygonConnect_20 [All vs IsNamedPolygon('CS') Or  IsNamedPolygon('C122_2') Or  IsNamedPolygon('PGND') Or  IsNamedPolygon('C101_2') Or  IsNamedPolygon('HVBUS') Or  IsNamedPolygon('CS') Or  IsNamedPolygon('RTN') Or  IsNamedPolygon('VBUS') Or  IsNamedPolygon('RTN') Or  IsNamedPolygon('C102_2') Or  IsNamedPolygon('C101_2') Or  IsNamedPolygon('VBUS') Or  IsNamedPolygon('C122_1') Or  IsNamedPolygon('C122_2') Or  IsNamedPolygon('C122_1') Or  IsNamedPolygon('Q101_2') Or  IsNamedPolygon('C102_2') Or  IsNamedPolygon('J105_1') Or  IsNamedPolygon('VBATT') Or  IsNamedPolygon('BATT_RTN') Or  IsNamedPolygon('C100_2') Or  IsNamedPolygon('VBATT') Or  IsNamedPolygon('C100_2') Or  IsNamedPolygon('SGND') Or  IsNamedPolygon('J105_1') Or  IsNamedPolygon('C100_1') Or  IsNamedPolygon('BATT_RTN') Or  IsNamedPolygon('C100_1') Or  IsNamedPolygon('C103_1') Or  IsNamedPolygon('C103_1')] p4: connectstyle=Direct reliefconductorwidth=10 reliefentries=4 polygonreliefangle="90 Angle" airgapwidth=10
PolygonConnect PolygonConnect_19 [All vs IsNamedPolygon('C100_1') Or  IsNamedPolygon('C100_1') Or  IsNamedPolygon('VBATT') Or  IsNamedPolygon('VBATT') Or  IsNamedPolygon('C103_1') Or  IsNamedPolygon('C103_1') Or  IsNamedPolygon('C100_2') Or  IsNamedPolygon('C100_2') Or  IsNamedPolygon('RTN') Or  IsNamedPolygon('RTN') Or  IsNamedPolygon('PGND') Or  IsNamedPolygon('C102_2') Or  IsNamedPolygon('C102_2') Or  IsNamedPolygon('C101_2') Or  IsNamedPolygon('C101_2') Or  IsNamedPolygon('CS') Or  IsNamedPolygon('CS') Or  IsNamedPolygon('C122_1') Or  IsNamedPolygon('C122_2') Or  IsNamedPolygon('C122_2') Or  IsNamedPolygon('C122_1') Or  IsNamedPolygon('Q101_2') Or  IsNamedPolygon('HVBUS') Or  IsNamedPolygon('VBUS') Or  IsNamedPolygon('VBUS')] p5: connectstyle=Direct reliefconductorwidth=10 reliefentries=4 polygonreliefangle="90 Angle" airgapwidth=10
PolygonConnect PolygonConnect_18 [All vs IsNamedPolygon('C103_1') Or  IsNamedPolygon('C101_2') Or  IsNamedPolygon('RTN') Or  IsNamedPolygon('PGND') Or  IsNamedPolygon('VBATT') Or  IsNamedPolygon('C100_2') Or  IsNamedPolygon('C101_2') Or  IsNamedPolygon('RTN') Or  IsNamedPolygon('C102_2') Or  IsNamedPolygon('C100_2') Or  IsNamedPolygon('C103_1') Or  IsNamedPolygon('C102_2') Or  IsNamedPolygon('VBATT') Or  IsNamedPolygon('CS') Or  IsNamedPolygon('CS') Or  IsNamedPolygon('C122_2') Or  IsNamedPolygon('C122_1') Or  IsNamedPolygon('VBUS') Or  IsNamedPolygon('C122_2') Or  IsNamedPolygon('Q101_2') Or  IsNamedPolygon('C122_1') Or  IsNamedPolygon('VBUS') Or  IsNamedPolygon('HVBUS')] p6: connectstyle=Direct reliefconductorwidth=10 reliefentries=4 polygonreliefangle="90 Angle" airgapwidth=10
PolygonConnect PolygonConnect_17 [All vs IsNamedPolygon('CS') Or  IsNamedPolygon('C102_2') Or  IsNamedPolygon('C122_2') Or  IsNamedPolygon('C101_2') Or  IsNamedPolygon('C122_1') Or  IsNamedPolygon('C102_2') Or  IsNamedPolygon('Q101_2') Or  IsNamedPolygon('VBUS') Or  IsNamedPolygon('C122_2') Or  IsNamedPolygon('C101_2') Or  IsNamedPolygon('RTN') Or  IsNamedPolygon('C122_1') Or  IsNamedPolygon('VBUS') Or  IsNamedPolygon('RTN') Or  IsNamedPolygon('PGND') Or  IsNamedPolygon('CS') Or  IsNamedPolygon('HVBUS')] p7: connectstyle=Direct reliefconductorwidth=10 reliefentries=4 polygonreliefangle="90 Angle" airgapwidth=10
PolygonConnect PolygonConnect_16 [All vs IsNamedPolygon('C122_2') Or  IsNamedPolygon('CS') Or  IsNamedPolygon('C122_1') Or  IsNamedPolygon('Q101_2') Or  IsNamedPolygon('VBUS') Or  IsNamedPolygon('VBUS') Or  IsNamedPolygon('HVBUS') Or  IsNamedPolygon('C122_2') Or  IsNamedPolygon('C122_1')] p8: connectstyle=Direct reliefconductorwidth=10 reliefentries=4 polygonreliefangle="90 Angle" airgapwidth=10
PolygonConnect PolygonConnect_15 [All vs IsNamedPolygon('C109_2') Or  IsNamedPolygon('C107_2') Or  IsNamedPolygon('HV') Or  IsNamedPolygon('Q203_5') Or  IsNamedPolygon('C107_2') Or  IsNamedPolygon('HS') Or  IsNamedPolygon('Q201_5') Or  IsNamedPolygon('Q203_5') Or  IsNamedPolygon('C106_2') Or  IsNamedPolygon('C108_2') Or  IsNamedPolygon('Vout') Or  IsNamedPolygon('Q203_5') Or  IsNamedPolygon('C108_2') Or  IsNamedPolygon('C113_2') Or  IsNamedPolygon('Q203_5') Or  IsNamedPolygon('Q201_5') Or  IsNamedPolygon('C107_2') Or  IsNamedPolygon('C102_1') Or  IsNamedPolygon('SGND') Or  IsNamedPolygon('GND') Or  IsNamedPolygon('SGND') Or  IsNamedPolygon('GND') Or  IsNamedPolygon('IN+') Or  IsNamedPolygon('IN+') Or  IsNamedPolygon('Q201_5') Or  IsNamedPolygon('Q201_5') Or  IsNamedPolygon('SGND') Or  IsNamedPolygon('SGND') Or  IsNamedPolygon('Vout') Or  IsNamedPolygon('Vout') Or  IsNamedPolygon('IN+') Or  IsNamedPolygon('GND') Or  IsNamedPolygon('IN+') Or  IsNamedPolygon('GND')] p9: connectstyle=Direct reliefconductorwidth=10 reliefentries=4 polygonreliefangle="90 Angle" airgapwidth=10
PolygonConnect PolygonConnect_14 [All vs IsNamedPolygon('C106_2') Or  IsNamedPolygon('C107_2') Or  IsNamedPolygon('C107_2') Or  IsNamedPolygon('C107_2') Or  IsNamedPolygon('C102_1') Or  IsNamedPolygon('Q203_5') Or  IsNamedPolygon('Vout') Or  IsNamedPolygon('Q203_5') Or  IsNamedPolygon('Q203_5') Or  IsNamedPolygon('Q201_5') Or  IsNamedPolygon('C108_2') Or  IsNamedPolygon('Q203_5') Or  IsNamedPolygon('HS') Or  IsNamedPolygon('HV') Or  IsNamedPolygon('C108_2') Or  IsNamedPolygon('Q201_5') Or  IsNamedPolygon('C109_2') Or  IsNamedPolygon('Q201_5') Or  IsNamedPolygon('Q201_5') Or  IsNamedPolygon('C113_2')] p10: connectstyle=Direct reliefconductorwidth=10 reliefentries=4 polygonreliefangle="90 Angle" airgapwidth=10
PolygonConnect PolygonConnect_13 [All vs IsNamedPolygon('C102_1') Or  IsNamedPolygon('HV') Or  IsNamedPolygon('C107_2') Or  IsNamedPolygon('C109_2') Or  IsNamedPolygon('C107_2') Or  IsNamedPolygon('C108_2') Or  IsNamedPolygon('C106_2') Or  IsNamedPolygon('C108_2') Or  IsNamedPolygon('C113_2') Or  IsNamedPolygon('C107_2')] p11: connectstyle=Direct reliefconductorwidth=10 reliefentries=4 polygonreliefangle="90 Angle" airgapwidth=10
PolygonConnect PolygonConnect_12 [All vs IsNamedPolygon('C107_2') Or  IsNamedPolygon('C113_2') Or  IsNamedPolygon('C106_2') Or  IsNamedPolygon('C107_2') Or  IsNamedPolygon('C107_2') Or  IsNamedPolygon('C102_1')] p12: connectstyle=Direct reliefconductorwidth=10 reliefentries=4 polygonreliefangle="90 Angle" airgapwidth=10
PolygonConnect PolygonConnect_11 [All vs IsNamedPolygon('C106_2') Or  IsNamedPolygon('C102_1') Or  IsNamedPolygon('C107_2') Or  IsNamedPolygon('C107_2') Or  IsNamedPolygon('C107_2')] p13: connectstyle=Direct reliefconductorwidth=10 reliefentries=4 polygonreliefangle="90 Angle" airgapwidth=10
PolygonConnect PolygonConnect_10 [All vs IsNamedPolygon('C106_2')] p14: connectstyle=Direct reliefconductorwidth=10 reliefentries=4 polygonreliefangle="90 Angle" airgapwidth=10
PolygonConnect PolygonConnect_9 [All vs IsNamedPolygon('C11_1') Or  IsNamedPolygon('Vin') Or  IsNamedPolygon('Vin') Or  IsNamedPolygon('5V') Or  IsNamedPolygon('D6_2') Or  IsNamedPolygon('Q3_3') Or  IsNamedPolygon('GND2') Or  IsNamedPolygon('GND2') Or  IsNamedPolygon('GND') Or  IsNamedPolygon('Q3_4') Or  IsNamedPolygon('12V5') Or  IsNamedPolygon('GND') Or  IsNamedPolygon('12V5') Or  IsNamedPolygon('D3_1')] p15: connectstyle=Direct reliefconductorwidth=10 reliefentries=4 polygonreliefangle="90 Angle" airgapwidth=10
PolygonConnect PolygonConnect_8 [All vs IsNamedPolygon('C11_1') Or  IsNamedPolygon('Vin') Or  IsNamedPolygon('12V5') Or  IsNamedPolygon('Q3_3') Or  IsNamedPolygon('GND2') Or  IsNamedPolygon('GND2') Or  IsNamedPolygon('5V') Or  IsNamedPolygon('Q3_4') Or  IsNamedPolygon('12V5')] p16: connectstyle=Direct reliefconductorwidth=10 reliefentries=4 polygonreliefangle="90 Angle" airgapwidth=10
PolygonConnect PolygonConnect_7 [All vs IsNamedPolygon('GND2') Or  IsNamedPolygon('GND2') Or  IsNamedPolygon('5V') Or  IsNamedPolygon('12V5') Or  IsNamedPolygon('12V5') Or  IsNamedPolygon('C11_1')] p17: connectstyle=Direct reliefconductorwidth=10 reliefentries=4 polygonreliefangle="90 Angle" airgapwidth=10
PolygonConnect PolygonConnect_6 [All vs IsNamedPolygon('GND2') Or  IsNamedPolygon('SGND') Or  IsNamedPolygon('GND1') Or  IsNamedPolygon('C901_1') Or  IsNamedPolygon('SGND') Or  IsNamedPolygon('GND2') Or  IsNamedPolygon('GND1')] p18: connectstyle=Direct reliefconductorwidth=10 reliefentries=4 polygonreliefangle="90 Angle" airgapwidth=10
PolygonConnect PolygonConnect_5 [All vs IsNamedPolygon('GND1') Or  IsNamedPolygon('GND1')] p19: connectstyle=Direct reliefconductorwidth=10 reliefentries=4 polygonreliefangle="90 Angle" airgapwidth=10
PolygonConnect PolygonConnect_4 [All vs IsNamedPolygon('C21_1') Or  IsNamedPolygon('C5_1') Or  IsNamedPolygon('C12_2') Or  IsNamedPolygon('C2_2') Or  IsNamedPolygon('C13_1') Or  IsNamedPolygon('C28_1') Or  IsNamedPolygon('C6_1') Or  IsNamedPolygon('GND') Or  IsNamedPolygon('GND2') Or  IsNamedPolygon('C14_1') Or  IsNamedPolygon('C13_1') Or  IsNamedPolygon('Q1_3') Or  IsNamedPolygon('C14_1') Or  IsNamedPolygon('C5_1') Or  IsNamedPolygon('GND2') Or  IsNamedPolygon('C28_1') Or  IsNamedPolygon('D5_2') Or  IsNamedPolygon('D6_2') Or  IsNamedPolygon('D2_1') Or  IsNamedPolygon('C12_2') Or  IsNamedPolygon('D2_1') Or  IsNamedPolygon('C4_1') Or  IsNamedPolygon('C4_1') Or  IsNamedPolygon('C2_2') Or  IsNamedPolygon('GND') Or  IsNamedPolygon('C33_1') Or  IsNamedPolygon('C9_1')] p20: connectstyle=Direct reliefconductorwidth=10 reliefentries=4 polygonreliefangle="90 Angle" airgapwidth=10
PolygonConnect PolygonConnect_3 [All vs IsNamedPolygon('C28_1') Or  IsNamedPolygon('C12_2') Or  IsNamedPolygon('C28_1') Or  IsNamedPolygon('C9_1') Or  IsNamedPolygon('D5_2') Or  IsNamedPolygon('C12_2') Or  IsNamedPolygon('C2_2') Or  IsNamedPolygon('C14_1') Or  IsNamedPolygon('C4_1') Or  IsNamedPolygon('C14_1') Or  IsNamedPolygon('D6_2') Or  IsNamedPolygon('GND2') Or  IsNamedPolygon('Q1_3') Or  IsNamedPolygon('C5_1') Or  IsNamedPolygon('D2_1') Or  IsNamedPolygon('C4_1') Or  IsNamedPolygon('C13_1') Or  IsNamedPolygon('C5_1') Or  IsNamedPolygon('C13_1') Or  IsNamedPolygon('C33_1') Or  IsNamedPolygon('D2_1') Or  IsNamedPolygon('GND') Or  IsNamedPolygon('GND') Or  IsNamedPolygon('GND2') Or  IsNamedPolygon('C2_2') Or  IsNamedPolygon('C6_1') Or  IsNamedPolygon('C21_1')] p21: connectstyle=Direct reliefconductorwidth=10 reliefentries=4 polygonreliefangle="90 Angle" airgapwidth=10
PolygonConnect PolygonConnect_2 [All vs IsNamedPolygon('C21_1') Or  IsNamedPolygon('C4_1') Or  IsNamedPolygon('D5_2') Or  IsNamedPolygon('C5_1') Or  IsNamedPolygon('C14_1') Or  IsNamedPolygon('C13_1') Or  IsNamedPolygon('C4_1') Or  IsNamedPolygon('C33_1') Or  IsNamedPolygon('C12_2') Or  IsNamedPolygon('D2_1') Or  IsNamedPolygon('C2_2') Or  IsNamedPolygon('C28_1') Or  IsNamedPolygon('C12_2') Or  IsNamedPolygon('D2_1') Or  IsNamedPolygon('C5_1') Or  IsNamedPolygon('Q1_3') Or  IsNamedPolygon('GND') Or  IsNamedPolygon('D6_2') Or  IsNamedPolygon('C6_1') Or  IsNamedPolygon('C2_2') Or  IsNamedPolygon('C14_1') Or  IsNamedPolygon('C28_1') Or  IsNamedPolygon('C13_1') Or  IsNamedPolygon('C9_1') Or  IsNamedPolygon('GND')] p22: connectstyle=Direct reliefconductorwidth=10 reliefentries=4 polygonreliefangle="90 Angle" airgapwidth=10
PolygonConnect PolygonConnect_1 [All vs IsNamedPolygon('C28_1') Or  IsNamedPolygon('D5_2') Or  IsNamedPolygon('C5_1') Or  IsNamedPolygon('C5_1') Or  IsNamedPolygon('D2_1') Or  IsNamedPolygon('C21_1') Or  IsNamedPolygon('C9_1') Or  IsNamedPolygon('C4_1') Or  IsNamedPolygon('C14_1') Or  IsNamedPolygon('C28_1') Or  IsNamedPolygon('C6_1') Or  IsNamedPolygon('C12_2') Or  IsNamedPolygon('C33_1') Or  IsNamedPolygon('C4_1') Or  IsNamedPolygon('C13_1') Or  IsNamedPolygon('C12_2') Or  IsNamedPolygon('D6_2') Or  IsNamedPolygon('C2_2') Or  IsNamedPolygon('C14_1') Or  IsNamedPolygon('D2_1') Or  IsNamedPolygon('C2_2') Or  IsNamedPolygon('C13_1')] p23: connectstyle=Direct reliefconductorwidth=10 reliefentries=4 polygonreliefangle="90 Angle" airgapwidth=10
PolygonConnect [All] p24: connectstyle=Relief reliefconductorwidth=10 reliefentries=4 polygonreliefangle="90 Angle" airgapwidth=10
RoutingVias ThermalPadVias [IsVia and InAnyComponent] p1: holewidth=7.87 width=19.68 viastyle="Through Hole" minholewidth=7.87 minwidth=19.68 maxholewidth=12.99 maxwidth=23.62
RoutingVias [All] p2: holewidth=16 width=34 viastyle="Through Hole" minholewidth=7.87 minwidth=20 maxholewidth=40 maxwidth=65
SilkToBoardRegionClearance [Not ((IsComment or IsDesignator) And (Hide <> 'False')) and not InRegion(1000,500,4000,800)] p1:
SilkToSilkClearance SilkToSilkClearance_Pb-FreeLogo [(HasFootprint('Pb-Free_Overlay_Medium') OR HasFootprint('Pb-Free_Overlay_Small')) vs (HasFootprint('Pb-Free_Overlay_Medium') OR HasFootprint('Pb-Free_Overlay_Small'))] p1: silktosilkclearance=0
SilkToSilkClearance [All] p2: silktosilkclearance=1
SilkToSolderMaskClearance "Silk to Solder Mask Opening" [All] p1: minsilkscreentomaskgap=1 clearancetoexposedcopper=FALSE
SolderMaskExpansion [All] p1: expansion=1.97
Width [All] p1: maxlimit=100 minlimit=6 preferedwidth=10 checkconnectedcopper=TRUE
14 further rules are at their usual default settings.

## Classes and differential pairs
component class Header: J203
component class "Mounting Holes": H200 H201 H202 H203
net class MV: NetR202_1
net class HV: G1H_P G1H_S G2H_P G2H_S HVBUS NetC100_1 NetC100_2 NetC101_2 NetC102_2 NetC103_1 NetC122_1 NetC122_2 NetD100_2 NetD101_2 NetD102_2 NetD103_2 NetJ105_1 NetQ100_4 NetQ101_2 NetQ101_4 NetQ102_4 NetQ103_4 NetR100_1 NetR101_1 NetR110_1 NetR111_1 S1H_P S1H_S S2H_P S2H_S VBATT VBUS
component class Controller: C200 C201 C202 C203 C204 C205 C206 C207 C208 C209 C210 C211 C212 C213 C214 C215 C216 C217 C218 C219 C220 C221 C222 C223 C224 C225 C226 C227 C228 C229 C230 C231 C232 C233 C234 C235 C236 C237 C238 C239 C240 C241 C242 C243 C244 C245 C246 C247 C248 C249 C250 C251 C252 C253 C254 D200 H200 H201 H202 H203 H204 H205 H206 H207 J200 J201 J202 J203 J204 J205 J206 J207 J209 R200 R201 R202 R203 R204 R205 R206 R207 R208 R209 R210 R211 R212 R213 R214 R215 R216 R217 R218 R219 R220 R221 R222 R223 R224 R225 R226 R227 R228 R229 R230 R231 R232 R233 R234 R235 R236 R237 R238 R239 R240 R241 R242 R243 R244 R245 R246 R247 R248 R249 R250 R251 R252 R253 R254 R255 R256 R257 R258 R259 R260 R261 R262 R263 R264 R265 TP108 TP109 TP200 TP201 TP202 TP203 TP204 TP205 TP206 TP207 TP208 TP209 TP210 TP211 TP212 TP213 TP214 TP215 U200 U201 U202 U203 U204 U205 U206 U207 U208 U209 U210 U211
component class PowerStage: !PCB100 C100 C101 C102 C103 C104 C105 C106 C107 C108 C109 C110 C111 C112 C113 C114 C115 C116 C117 C118 C119 C120 C121 C122 C123 C124 C125 C126 C127 C128 C129 C130 C131 C132 C133 C134 C135 C136 C137 C138 C139 C140 C141 C142 C146 C147 C148 C149 C158 D100 D101 D102 D103 D104 D105 D106 D107 F100 F101 H100 H101 H102 H103 H104 H105 H106 H107 J100 J101 J102 J103 J104 J105 Logo2 Logo3 LOGO100 LOGO101 LOGO102 LOGO104 Q100 Q101 Q102 Q103 Q104 Q105 Q106 Q107 R100 R101 R102 R103 R104 R105 R106 R107 R108 R109 R110 R111 R112 R113 R114 R115 R116 R117 R118 R119 R120 R121 R122 R123 R124 R125 R126 R127 R128 R129 R130 R131 R132 R133 R134 R135 R136 R137 R138 R139 R140 R141 R142 R143 R144 R145 R146 T100 TP100 TP101 TP102 TP103 TP105 TP106 TP107 XF100 XF101 XF102 XF103 ""

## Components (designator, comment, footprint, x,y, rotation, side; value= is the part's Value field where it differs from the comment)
C100 "" 1206_190 8225.2,540 r90 top value=8200pF
C101 "400BXW150MEFC16X45" FC_1600x4000 1370,700 r90 top value=150uF
C102 "400BXW150MEFC16X45" FC_1600x4000 1370,2250 r90 top value=150uF
C103 "500MXG150MEFCSN22X55" Nichicon_2200x4500_Snap 10210,3670 r270 top value=150uF
C104 "500MXG150MEFCSN22X55" Nichicon_2200x4500_Snap 10210,2670 r270 top value=150uF
C105 "" 1206_190 8315.2,540 r90 top value=8200pF
C106 "500MXG150MEFCSN22X55" Nichicon_2200x4500_Snap 10210,1670 r270 top value=150uF
C107 "500MXG150MEFCSN22X55" Nichicon_2200x4500_Snap 10210,670 r270 top value=150uF
C108 "" 1206_190 8405.2,540 r90 top value=8200pF
C109 "" 1206_190 8495.2,540 r90 top value=8200pF
C110 "" 1206_190 8585.2,540 r90 top value=8200pF
C111 "400BXW150MEFC16X45" FC_1600x4000 1370,1460 r90 top value=150uF
C112 "400BXW150MEFC16X45" FC_1600x4000 1370,3010 r90 top value=150uF
C113 "" 1206_190 8675.2,540 r90 top value=8200pF
C114 "" 1206_190 8800,685.2 r180 top value=8200pF
C115 "" 1206_190 8800,775.2 r180 top value=8200pF
C116 "" 1206_190 8800,862.6 r180 top value=8200pF
C117 "" 1206_190 8800,952.6 r180 top value=8200pF
C118 "" 1206_190 8800,1042.6 r180 top value=8200pF
C119 "" 1206_190 8800,1132.6 r180 top value=8200pF
C120 "" 1206_190 8800,1135.2 r180 bottom value=8200pF
C121 "" 1206_190 8800,1045.83 r180 bottom value=8200pF
C122 "" 1206_190 3040,2680 r180 top value=8200pF
C123 "" 1206_190 8800,955.83 r180 bottom value=8200pF
C124 "" 1206_190 3040,2780 r180 top value=8200pF
C125 "" 1206_190 8800,865.83 r180 bottom value=8200pF
C126 "" 1206_190 3040,2580 r180 top value=8200pF
C127 "" 1206_190 8800,775.83 r180 bottom value=8200pF
C128 "" 1206_190 3040,2380 r180 top value=8200pF
C129 "" 1206_190 8800,685.83 r180 bottom value=8200pF
C130 "1812Y1K00104KSTWS2" 1812_254 1500,2170 r90 bottom value=0.1uF
C131 "1812Y1K00104KSTWS2" 1812_254 1660,2150 r90 bottom value=0.1uF
C132 "B58031I5105M002" B58031I_1084x785x450 10210,3180 r0 bottom value=1uF
C133 "B58031I5105M002" B58031I_1084x785x450 10240,2220 r0 bottom value=1uF
C134 "" 1206_190 3040,2480 r180 top value=8200pF
C135 "" 1206_190 8675.83,540 r90 bottom value=8200pF
C136 "" 1206_190 3040,3180 r180 top value=8200pF
C137 "" 1206_190 8585.83,540 r90 bottom value=8200pF
C138 "" 1206_190 3040,3280 r180 top value=8200pF
C139 "" 1206_190 8495.83,540 r90 bottom value=8200pF
C140 "" 1206_190 3040,3080 r180 top value=8200pF
C141 "" 1206_190 8405.83,540 r90 bottom value=8200pF
C142 "B58031I5105M002" B58031I_1084x785x450 10450,1130 r90 bottom value=1uF
C146 "" 1206_190 3040,2880 r180 top value=8200pF
C147 "" 1206_190 8315.83,540 r90 bottom value=8200pF
C148 "" 1206_190 3040,2980 r180 top value=8200pF
C149 "" 1206_190 8225.83,540 r90 bottom value=8200pF
C158 "DE1E3KX222MA4BL01" CAPRD1000W60D900H1200 5900,270 r180 top value=2200pF
C200 "GRM155R60J222KA01D" 0402 4240,5240 r0 top value=2200pF
C201 "GCM188R71C104KA37J" 0603 1880,3200 r180 top value=0.1uF
C202 "06033C104JAT2A" 0603 4274.41,4740.98 r180 top value=0.1uF
C203 "CGA2B2X7R1H471K050BA" 0402 4070,4560 r0 top value=470pF
C204 "C0603C100J5GACTU" 0603 4100,5147.13 r0 top value=10pF
C205 "06033C104JAT2A" 0603 3980,5147.13 r180 top value=0.1uF
C206 "CGA2B2X7R1H471K050BA" 0402 3454.41,5158.35 r0 top value=470pF
C207 "CGA2B2X7R1H471K050BA" 0402 3344.41,5158.35 r180 top value=470pF
C208 "GRM155R61A103KA01D" 0402 3900.95,5354.26 r270 top value=0.01uF
C209 "C1608X7R1E105K080AB" 0603 10290,4660 r270 top value=1uF
C210 "CGB3B1X5R1A475K055AC" 0603 10140,5290 r0 top value=4.7uF
C211 "GCM188R71C104KA37J" 0603 10140,5230 r0 top value=0.1uF
C212 "C1005X7R1E104M050BB" 0402 3807.32,5214.26 r180 top value=0.1uF
C213 "C1005X7R1E104M050BB" 0402 9150,5160 r0 top value=0.1uF
C214 "C1005X7R1E104M050BB" 0402 9590,4630 r0 top value=0.1uF
C215 "06031C103KAT2A" 0603 10140,4610 r0 top value=0.01uF
C216 "GRM155R61A103KA01D" 0402 3670,5437.13 r0 top value=0.01uF
C217 "GRM155R61A103KA01D" 0402 3782.87,5487.13 r0 top value=0.01uF
C218 "C1608X7R1E105K080AB" 0603 3980,5497.13 r0 top value=1uF
C219 "C1005X7R1E104M050BB" 0402 9590,5160 r0 top value=0.1uF
C220 "GRM155R70J104KA01D" 0402 4050,5597.13 r90 top value=0.1uF
C221 "GRM155R61A103KA01D" 0402 4534.41,4590.98 r270 top value=0.01uF
C222 "GRM155R70J104KA01D" 0402 3850,5637.13 r270 top value=0.1uF
C223 "C1608X7R1E105K080AB" 0603 9770,4620 r0 top value=1uF
C224 "CGB3B1X5R1A475K055AC" 0603 9900,5290 r0 top value=4.7uF
C225 "GCM188R71C104KA37J" 0603 9900,5230 r0 top value=0.1uF
C226 "C1005X7R1E104M050BB" 0402 4454.41,4720.98 r180 top value=0.1uF
C227 "GCM188R71C104KA37J" 0603 4440,5637.13 r180 top value=0.1uF
C228 "06031C103KAT2A" 0603 9900,4620 r0 top value=0.01uF
C229 "GRM155R61A103KA01D" 0402 4424.41,4417.22 r180 top value=0.01uF
C230 "GCM188R71C104KA37J" 0603 4310,5637.13 r0 top value=0.1uF
C231 "GCM188R71C104KA37J" 0603 4370,5397.13 r0 top value=0.1uF
C232 "GRM155R61A103KA01D" 0402 4314.41,4590.98 r90 top value=0.01uF
C233 "C1005X7R1E104M050BB" 0402 9140,4630 r0 top value=0.1uF
C234 "GRM1555C1H220FA01D" 0402 9380,5160 r180 top value=22pF
C235 "GRM1555C1H220FA01D" 0402 9510,5190 r90 top value=22pF
C236 "GRM1555C1H220FA01D" 0402 8940,5160 r180 top value=22pF
C237 "GRM1555C1H220FA01D" 0402 9070,5190 r90 top value=22pF
C238 "GRM188C80J225KE19D" 0603 4940,4850 r270 top value=2.2uF
C239 "GRM1555C1H221JA01D" 0402 4280,4890 r0 bottom value=220pF
C240 "06033C104JAT2A" 0603 4280,4830 r0 bottom value=0.1uF
C241 "C1005X7R1E104M050BB" 0402 4140,4730 r180 top value=0.1uF
C242 "C0402C100C8GACTU" 0402 4040,4730 r180 top value=10pF
C243 "08053C104JAT2A" 0805_HV 4160,4490 r180 top value=0.1uF
C244 "C0402C100C8GACTU" 0402 3840,4730 r180 top value=10pF
C245 "C0402C100C8GACTU" 0402 3940,4730 r180 top value=10pF
C246 "GRM1555C1H2R2BA01D" 0402 3910,4327.72 r0 top value=2.2pF
C247 "0402YC104KAT2A" 0402 3900,4552.87 r180 top value=0.1uF
C248 "CGA2B2X7R1H222K050BA" 0402 3780,4310 r180 top value=2200pF
C249 "0402YC104KAT2A" 0402 3780,4430 r90 top value=0.1uF
C250 "GRM1555C1H2R2BA01D" 0402 3873.37,5171.89 r90 bottom value=2.2pF
C251 "0402YC104KAT2A" 0402 4110,5170 r270 bottom value=0.1uF
C252 "CGA2B2X7R1H222K050BA" 0402 3830,5010 r270 bottom value=2200pF
C253 "0402YC104KAT2A" 0402 3990,5050.42 r0 bottom value=0.1uF
C254 "C0402C100C8GACTU" 0402 4090,5010 r0 bottom value=10pF
D100 "CUS05S40,H3F" SOD-323 2690,2880 r0 top value=40V
D101 "CUS05S40,H3F" SOD-323 2710,1240 r0 top value=40V
D102 "CUS05S40,H3F" SOD-323 9300,540 r270 top value=40V
D103 "CUS05S40,H3F" SOD-323 9141.36,2380 r180 top value=40V
D104 "CUS05S40,H3F" SOD-323 2690,3610 r0 top value=40V
D105 "CUS05S40,H3F" SOD-323 2700,2050 r0 top value=40V
D106 "CUS05S40,H3F" SOD-323 9300,1380 r90 top value=40V
D107 "CUS05S40,H3F" SOD-323 9290,3262.48 r90 top value=40V
D200 "BAT54S-7-F" SOT-23 5050,4860 r90 top value=30V
H200 "NY PMS 440 0025 PH" "NY PMS 440 0025 PH" 4100,250 r0 top
H201 "NY PMS 440 0025 PH" "NY PMS 440 0025 PH" 7400,250 r0 top
H202 "NY PMS 440 0025 PH" "NY PMS 440 0025 PH" 10510,4900 r0 top
H203 "NY PMS 440 0025 PH" "NY PMS 440 0025 PH" 850,5550 r0 top
H204 "1902C" Keystone_1902C 4099.77,250.01 r0 top
H205 "1902C" Keystone_1902C 7400,250 r0 top
H206 "1902C" Keystone_1902C 10509.77,4900.01 r0 top
H207 "1902C" Keystone_1902C 850,5550 r0 top
J100 "282856-2" TE_282856-2 700,3160 r270 top
J101 "282856-3" TE_282856-3 11000,3180 r90 top
J102 "282856-3" TE_282856-3 11000,4230 r90 top
J103 "282856-2" TE_282856-2 700,3914.96 r270 top
J104 "575-4" Keystone_575-4#1 8400,900 r0 top
J105 "575-4" Keystone_575-4#2 8400,3750 r0 top
J200 "215307-3" TE_215307-3 2429,3830 r270 top
J201 "215307-3" TE_215307-3 2429,2300 r270 top
J202 "HSEC8-160-01-L-DV-A-BL" controlCARD-120HSEC 3504.41,4940.98 r180 top locked
J203 "61300511021" Wurth_61300511021 2750,5610 r180 top
J204 "215307-3" TE_215307-3 9531,2020 r90 top
J205 "215307-3" TE_215307-3 9531,3900 r90 top
J206 "SSW-104-24-G-D" Samtec_SSW-104-24-x-D 7680,4620 r180 top
J207 "HSEC8-130-01-L-DV-A" controlCARD-180HSEC-60pinAddon 1156.26,4940.98 r180 top locked
J209 "215307-3" TE_215307-3 6830,4620 r180 top
Logo2 "Pb-Free Symbol" Pb-Free_Overlay_Medium 8010,4360 r0 top
Logo3 "FCC disclaimer" FCC_disclaimer 4920,-360 r90 top
Logo4 "WEEE logo" WEEE_Minimum 3440,230 r0 top
LOGO100 "CAUTION HOT SURFACE" IEC_HotSurface_Medium 8090,5570 r0 top
LOGO101 "DANGER HIGH VOLTAGE" IEC_HighVoltage_Medium 6880,5570 r0 top
LOGO102 "DANGER HIGH VOLTAGE" IEC_HighVoltage_Medium 1170,4350 r0 top
LOGO104 "DANGER HIGH VOLTAGE" IEC_HighVoltage_Medium 10950,4880 r0 top
Q100 "C3M0030090K" TO-247-4 2700,2430 r90 bottom value=900V
Q101 "C3M0030090K" TO-247-4 2700,880 r90 bottom value=900V
Q102 "C3M0030090K" TO-247-4 9250,880 r270 bottom value=900V
Q103 "C3M0030090K" TO-247-4 9250,2760 r270 bottom value=900V
Q104 "C3M0030090K" TO-247-4 2700,3250 r90 bottom value=900V
Q105 "C3M0030090K" TO-247-4 2700,1700 r90 bottom value=900V
Q106 "C3M0030090K" TO-247-4 9250,1700 r270 bottom value=900V
Q107 "C3M0030090K" TO-247-4 9250,3580 r270 bottom value=900V
R100 "CRCW12061M00FKEA" 1206 1240,590 r270 bottom value=1.00Meg
R101 "CRCW12061M00FKEA" 1206 1250,2143.09 r270 bottom value=1.00Meg
R102 "" CSNL1206 10366.4,4240.65 r270 top value=0.006
R103 "WSLP1206R0100FEA" 1206 1230,3460 r90 top value=0.01
R104 "" CSNL1206 10726.4,4240.65 r270 top value=0.006
R105 "CRCW12061M00FKEA" 1206 1240,800 r270 bottom value=1.00Meg
R106 "CRCW12061M00FKEA" 1206 1250,2353.09 r270 bottom value=1.00Meg
R107 "WSLP1206R0100FEA" 1206 1130,3460 r90 top value=0.01
R108 "" CSNL1206 10636.4,4240.65 r270 top value=0.006
R109 "WSLP1206R0100FEA" 1206 1330,3460 r90 top value=0.01
R110 "CRCW12061M00FKEA" 1206 1240,1350 r270 bottom value=1.00Meg
R111 "CRCW12061M00FKEA" 1206 1250,2900 r270 bottom value=1.00Meg
R112 "" CSNL1206 10546.4,4240.65 r270 top value=0.006
R113 "WSLP1206R0100FEA" 1206 1530,3460 r90 top value=0.01
R114 "CRCW12061M00FKEA" 1206 1240,1560 r270 bottom value=1.00Meg
R115 "CRCW12061M00FKEA" 1206 1250,3110 r270 bottom value=1.00Meg
R116 "" CSNL1206 10456.4,4240.04 r270 top value=0.006
R117 "WSLP1206R0100FEA" 1206 1430,3460 r90 top value=0.01
R118 "CRCW06035R11FKEA" 0603 2690,2810 r0 top value=5.11
R119 "CRCW06035R11FKEA" 0603 2710,1170 r0 top value=5.11
R120 "CRCW06035R11FKEA" 0603 9200,589.67 r180 top value=5.11
R121 "CRCW06035R11FKEA" 0603 9171.36,2480 r90 top value=5.11
R122 "RC0603FR-071RL" 0603 2770,2710 r270 top value=1.00
R123 "RC0603FR-071RL" 0603 2807.18,1160 r270 top value=1.00
R124 "RC0603FR-071RL" 0603 9200,529.67 r180 top value=1.00
R125 "RC0603FR-071RL" 0603 9111.36,2480 r90 top value=1.00
R126 "CRCW060310K0FKEA" 0603 2655.55,2720 r0 top value=10.0k
R127 "CRCW060310K0FKEA" 0603 2807.09,1027.91 r90 top value=10.0k
R128 "CRCW060310K0FKEA" 0603 9170,730 r270 top value=10.0k
R129 "CRCW060310K0FKEA" 0603 9170,2610 r270 top value=10.0k
R130 "CRCW06035R11FKEA" 0603 2680,3540 r0 top value=5.11
R131 "CRCW06035R11FKEA" 0603 2690,1980 r0 top value=5.11
R132 "CRCW06035R11FKEA" 0603 9200,1350 r180 top value=5.11
R133 "CRCW06035R11FKEA" 0603 9190,3231.46 r180 top value=5.11
R134 "RC0603FR-071RL" 0603 2790,3580 r270 top value=1.00
R135 "RC0603FR-071RL" 0603 2790,1980 r270 top value=1.00
R136 "RC0603FR-071RL" 0603 9200,1410 r180 top value=1.00
R137 "RC0603FR-071RL" 0603 9190,3291.46 r180 top value=1.00
R138 "CRCW060310K0FKEA" 0603 2790,3400 r90 top value=10.0k
R139 "CRCW060310K0FKEA" 0603 2788.39,1850 r90 top value=10.0k
R140 "CRCW060310K0FKEA" 0603 9170,1560 r270 top value=10.0k
R141 "CRCW060310K0FKEA" 0603 9170,3430 r270 top value=10.0k
R142 "WSLP1206R0100FEA" 1206 1860,2598.66 r0 top value=0.01
R143 "WSLP1206R0100FEA" 1206 1860,2698.66 r0 top value=0.01
R144 "WSLP1206R0100FEA" 1206 1860,2498.66 r0 top value=0.01
R145 "WSLP1206R0100FEA" 1206 1860,2298.66 r0 top value=0.01
R146 "WSLP1206R0100FEA" 1206 1860,2398.66 r0 top value=0.01
R200 "CRCW04020000Z0ED" 0402 9460,5190 r270 top value=0
R201 "CRCW04020000Z0ED" 0402 9020,5190 r270 top value=0
R202 "CRCW1206365KFKEA" 1206 1680,4560 r180 top value=365k
R203 "CRCW040256R2FKED" 0402 4290,5290 r180 top value=56.2
R204 "ERJ-2RKF2403X" 0402 1970,2980 r270 top value=240k
R205 "CRCW1206365KFKEA" 1206 1890,4560 r180 top value=365k
R206 "CRCW080528K7FKEA" 0805_HV 4290,5160 r0 top value=28.7k
R207 "CRCW040256R2FKED" 0402 4350,5240 r180 top value=56.2
R208 "CRCW040210K0FKED" 0402 1970,3200 r90 top value=10.0k
R209 "CRCW060325R5FKEA" 0603 4274.41,4680.98 r0 top value=25.5
R210 "CRCW1206365KFKEA" 1206 2100,4560 r180 top value=365k
R211 "CRCW04021K24FKED" 0402 4190,5170 r270 top value=1.24k
R212 "CRCW060356R2FKEA" 0603 4100,5207.13 r180 top value=56.2
R213 "CRCW040210K0FKED" 0402 1820,2980 r270 top value=10.0k
R214 "CRCW06035K49FKEA" 0603 4060,4620 r180 top value=5.49k
R215 "ERJ-2RKF2403X" 0402 1870,2980 r90 top value=240k
R216 "CRCW040210K0FKED" 0402 1920,2980 r90 top value=10.0k
R217 "CRCW040210K0FKED" 0402 1970,3090 r90 top value=10.0k
R218 "CRCW060325R5FKEA" 0603 3980,5207.13 r180 top value=25.5
R219 "CRCW04020000Z0ED" 0402 9410,5240 r270 top value=0
R220 "CRCW04020000Z0ED" 0402 8970,5240 r270 top value=0
R221 "CRCW04024K99FKED" 0402 3454.41,5258.35 r0 top value=4.99k
R222 "CRCW04024K99FKED" 0402 3344.41,5258.35 r180 top value=4.99k
R223 "CRCW04029K31FKED" 0402 3454.41,5208.35 r180 top value=9.31k
R224 "CRCW04029K31FKED" 0402 3344.41,5208.35 r0 top value=9.31k
R225 "CRCW06037K15FKEA" 0603 3950.95,5354.26 r90 top value=7.15k
R226 "CRCW060314K3FKEA" 0603 4880,4980 r90 top value=14.3k
R227 "CRCW06031K00FKEA" 0603 4880,4850 r90 top value=1.00k
R228 "CRCW060325R5FKEA" 0603 4160,4640 r270 top value=25.5
R229 "CRCW040256R2FKED" 0402 4040,4680 r0 top value=56.2
R230 "CRCW060339R2FKEA" 0603 10210,4480 r180 top value=39.2
R231 "CRG0402F4K7" 0402 3640,5517.13 r270 top value=4.70k
R232 "CRG0402F4K7" 0402 3648.35,5357.13 r270 top value=4.70k
R233 "CRG0402F4K7" 0402 3690,5517.13 r270 top value=4.70k
R234 "CRG0402F4K7" 0402 3698.35,5357.13 r270 top value=4.70k
R235 "CRCW060339R2FKEA" 0603 10210,4540 r180 top value=39.2
R236 "CRCW04027K15FKED" 0402 3782.87,5437.13 r180 top value=7.15k
R237 "RC1206FR-072ML" 1206 10110,4270 r0 top value=2.00Meg
R238 "CRCW06038K25FKEA" 0603 4584.41,4590.98 r90 top value=8.25k
R239 "RC1206FR-072ML" 1206 9910,4270 r0 top value=2.00Meg
R240 "RC1206FR-072ML" 1206 9800,4370 r0 top value=2.00Meg
R241 "CRCW06030000Z0EA" 0603 9770,4562.8 r0 top value=0
R242 "CRCW06032K55FKEA" 0603 4550,4470 r180 top value=2.55k
R243 "CRCW06032K55FKEA" 0603 4454.41,4497.22 r90 top value=2.55k
R244 "CRCW06032K55FKEA" 0603 4424.41,4366.73 r180 top value=2.55k
R245 "CRCW06032K55FKEA" 0603 4394.41,4497.22 r90 top value=2.55k
R246 "CRCW060325K5FKEA" 0603 9770,4502.8 r180 top value=25.5k
R247 "CRCW06030000Z0EA" 0603 9900,4560 r180 top value=0
R248 "CRCW06038K25FKEA" 0603 4264.41,4590.98 r270 top value=8.25k
R249 "CRCW06030000Z0EA" 0603 2750,5490 r90 top value=0
R250 "CRCW06030000Z0EA" 0603 2550,5490 r90 top value=0
R251 "CRCW06030000Z0EA" 0603 2650,5490 r90 top value=0
R252 "CRCW06030000Z0EA" 0603 2950,5480 r270 top value=0
R253 "CRCW040256R2FKED" 0402 3840,4680 r180 top value=56.2
R254 "CRCW040256R2FKED" 0402 3940,4680 r180 top value=56.2
R255 "CRCW04023K65FKED" 0402 3910,4371.65 r180 top value=3.65k
R256 "CRCW040210K0FKED" 0402 3780,4350 r0 top value=10.0k
R257 "CRCW04021K00FKED" 0402 3780,4270 r0 top value=1.00k
R258 "CRCW040210K0FKED" 0402 3910,4285 r180 top value=10.0k
R259 "CRCW040210K0FKED" 0402 3740,4430 r270 top value=10.0k
R260 "CRCW04023K65FKED" 0402 3920,5171.89 r270 bottom value=3.65k
R261 "CRCW040210K0FKED" 0402 3900,5100 r180 bottom value=10.0k
R262 "CRCW04021K00FKED" 0402 3780,5010 r90 bottom value=1.00k
R263 "CRCW040210K0FKED" 0402 3780,5110 r270 bottom value=10.0k
R264 "CRCW040256R2FKED" 0402 4090,5050.35 r0 bottom value=56.2
R265 "CRCW040210K0FKED" 0402 3990,5008.19 r180 bottom value=10.0k
T100 "60518" Payton_60518 6017.09,2330 r0 top locked value=25uH
TP100 "5000" Keystone5000 750,200 r90 top
TP101 "5000" Keystone5000 10750,250 r90 top
TP102 "5001" Keystone5001 11000,3800 r90 top
TP103 "5001" Keystone5001 700,4250 r90 top
TP105 "5001" Keystone5001 8490,4510 r90 top
TP106 "5001" Keystone5001 1880,4170 r90 top
TP107 "5001" Keystone5001 6060,4970 r90 top
TP108 "5001" Keystone5001 8240,4510 r90 top
TP109 "5000" Keystone5000 6300,4970 r90 top
TP200 "Suggest using a net name here" Mill-Max_0312-0-15-15-34-27-10-0 2560,3550 r90 top
TP201 "Suggest using a net name here" Mill-Max_0312-0-15-15-34-27-10-0 2560,2020 r90 top
TP202 "Suggest using a net name here" Mill-Max_0312-0-15-15-34-27-10-0 2560,3370 r90 top
TP203 "Suggest using a net name here" Mill-Max_0312-0-15-15-34-27-10-0 2560,1840 r90 top
TP204 "Suggest using a net name here" Mill-Max_0312-0-15-15-34-27-10-0 2560,2810 r90 top
TP205 "Suggest using a net name here" Mill-Max_0312-0-15-15-34-27-10-0 2560,1280 r90 top
TP206 "Suggest using a net name here" Mill-Max_0312-0-15-15-34-27-10-0 2560,2620 r90 top locked
TP207 "Suggest using a net name here" Mill-Max_0312-0-15-15-34-27-10-0 2560,1090 r90 top
TP208 "Suggest using a net name here" Mill-Max_0312-0-15-15-34-27-10-0 9400,1350 r90 top
TP209 "Suggest using a net name here" Mill-Max_0312-0-15-15-34-27-10-0 9400,3230 r90 top
TP210 "Suggest using a net name here" Mill-Max_0312-0-15-15-34-27-10-0 9400,1540 r90 top
TP211 "Suggest using a net name here" Mill-Max_0312-0-15-15-34-27-10-0 9400,3420 r90 top
TP212 "Suggest using a net name here" Mill-Max_0312-0-15-15-34-27-10-0 9400,610 r90 top
TP213 "Suggest using a net name here" Mill-Max_0312-0-15-15-34-27-10-0 9400,2490 r90 top
TP214 "Suggest using a net name here" Mill-Max_0312-0-15-15-34-27-10-0 9400,790 r90 top
TP215 "Suggest using a net name here" Mill-Max_0312-0-15-15-34-27-10-0 9400,2670 r90 top
U200 "OPA836IDBVT" DBV0006A_L 1870,3100 r0 top
U201 "OPA320AIDBVR" DBV0005A_N 3800.95,5324.26 r270 top
U202 "TLV71333PQDBVRQ1" DBV0005A_N 3950,5617.13 r270 top
U203 "AMC1302QDWVRQ1" DWV0008A 10139.49,4908.03 r90 top
U204 "ISO7820FDWR" DW0016B_HV 9460,4900 r270 top
U205 "REF2033AIDDCR" DDC0005A_N 4380,5517.13 r90 top
U206 "OPA320AIDBVR" DBV0005A_N 4424.41,4630.98 r0 top
U207 "AMC1311BDWVR" DWV0008A 9890,4910 r90 top
U208 "ISO7820FDWR" DW0016B_HV 9010,4900 r270 top
U209 "OPA320AIDBVR" DBV0005A_N 4110,4360 r270 top
U210 "OPA836IDBVT" DBV0006A_L 3880,4460 r0 top
U211 "OPA836IDBVT" DBV0006A_L 4014.45,5150 r90 bottom
XF100 "1A3400-10" Eaton_1A3400-10 760,2550 r90 top
XF101 "1A3400-10" Eaton_1A3400-10 760,570 r90 top
XF102 "1A3400-10" Eaton_1A3400-10 10940,560 r270 top
XF103 "1A3400-10" Eaton_1A3400-10 10940,2540 r270 top

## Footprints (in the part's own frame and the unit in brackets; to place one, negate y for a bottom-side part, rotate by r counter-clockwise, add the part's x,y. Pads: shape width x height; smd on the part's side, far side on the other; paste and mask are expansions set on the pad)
0402 [mm] "0402 from SM-752 data"
  rect 0.8x0.6 smd: 1(-0.6,0) 2(0.6,0)
  silkscreen extent -1.22,-0.52 1.22,0.52, body extent -0.55,-0.3 0.55,0.3, height 0.6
